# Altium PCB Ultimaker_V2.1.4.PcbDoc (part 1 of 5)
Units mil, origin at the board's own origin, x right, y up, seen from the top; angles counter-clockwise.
Board outline 6889.76 x 3110.24 mil, 4 copper layers (top, signal, Power, bot (thermal)), stack 67.717 mil thick; 574 components, 252 nets, 1322 pads, 511 vias.
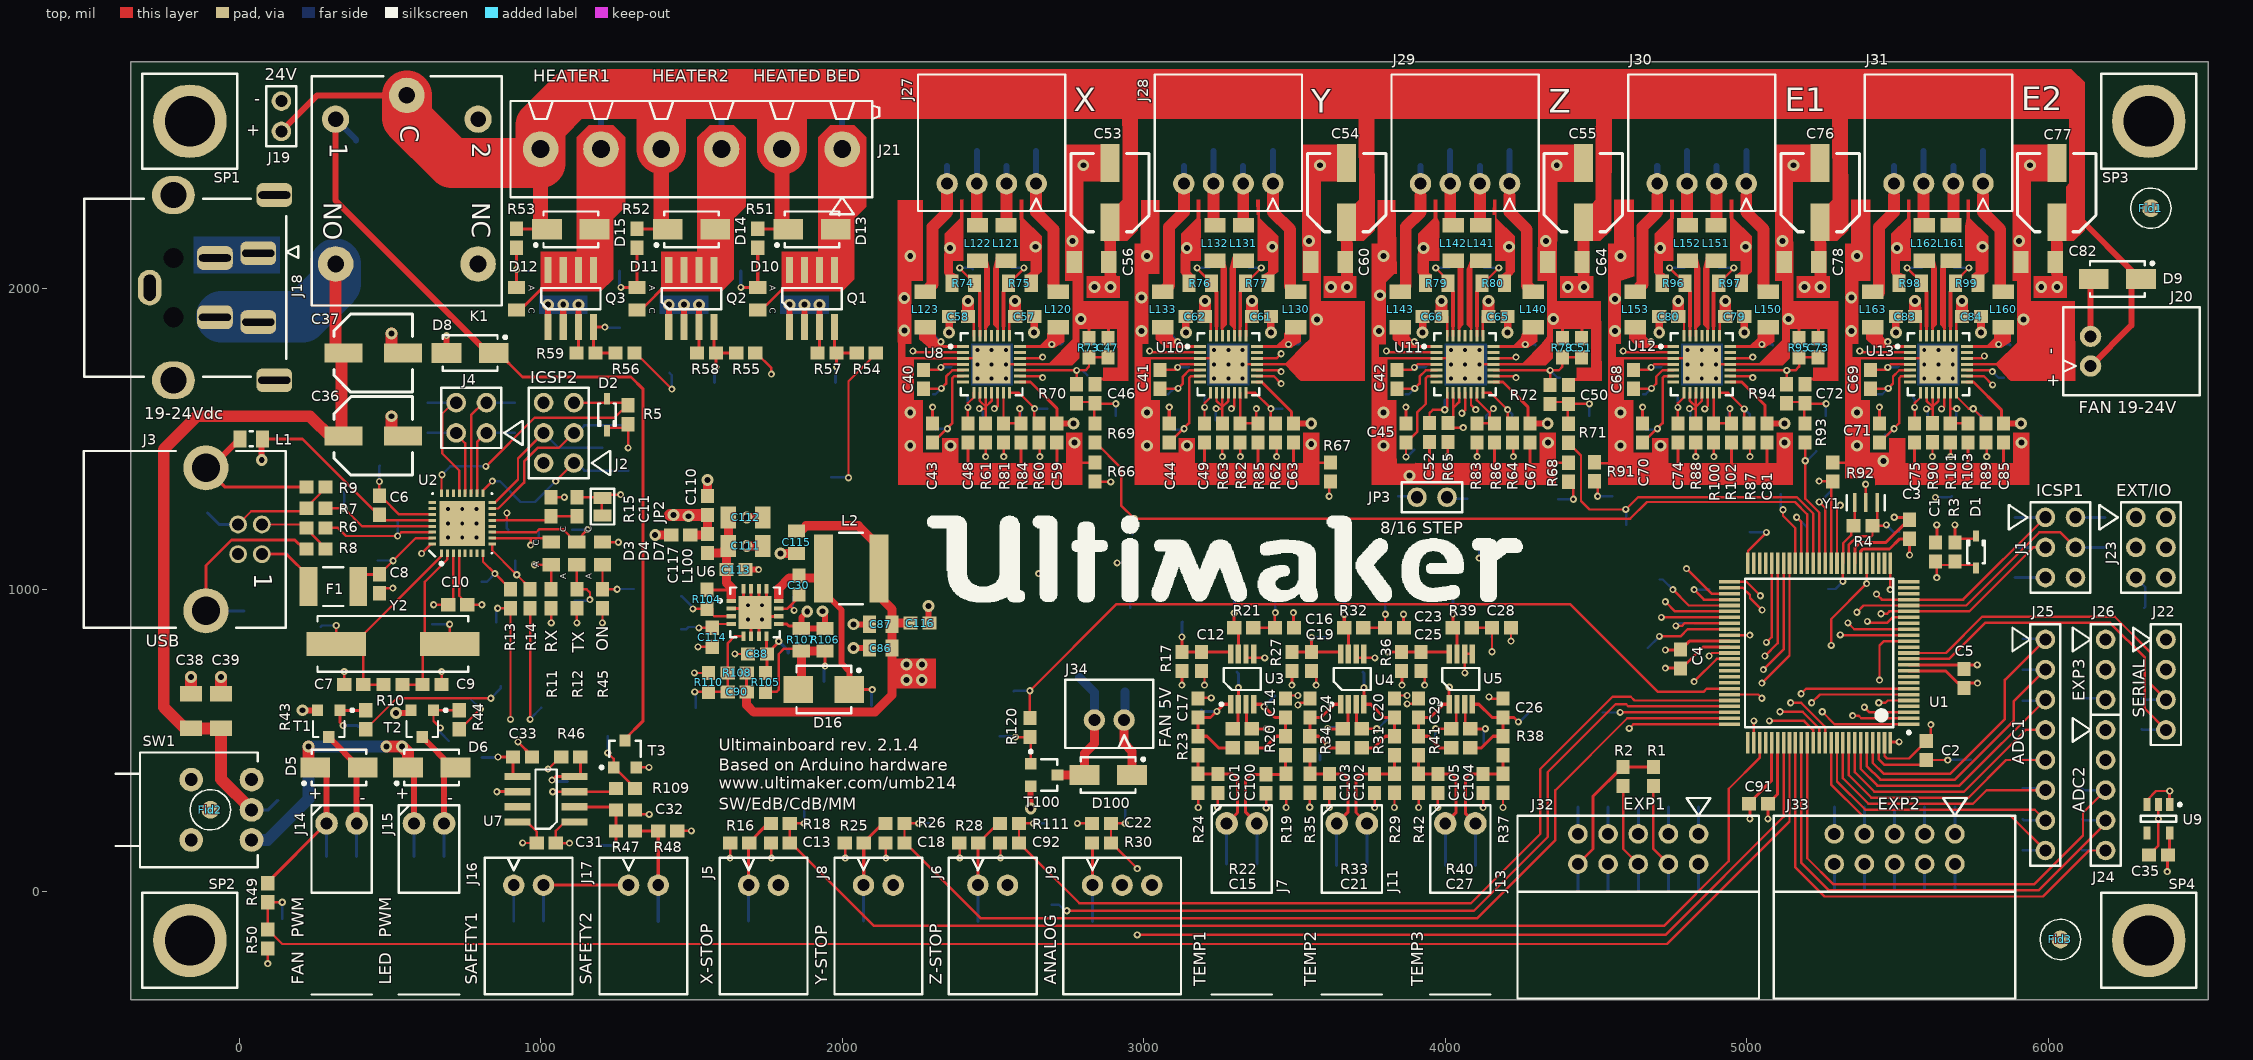
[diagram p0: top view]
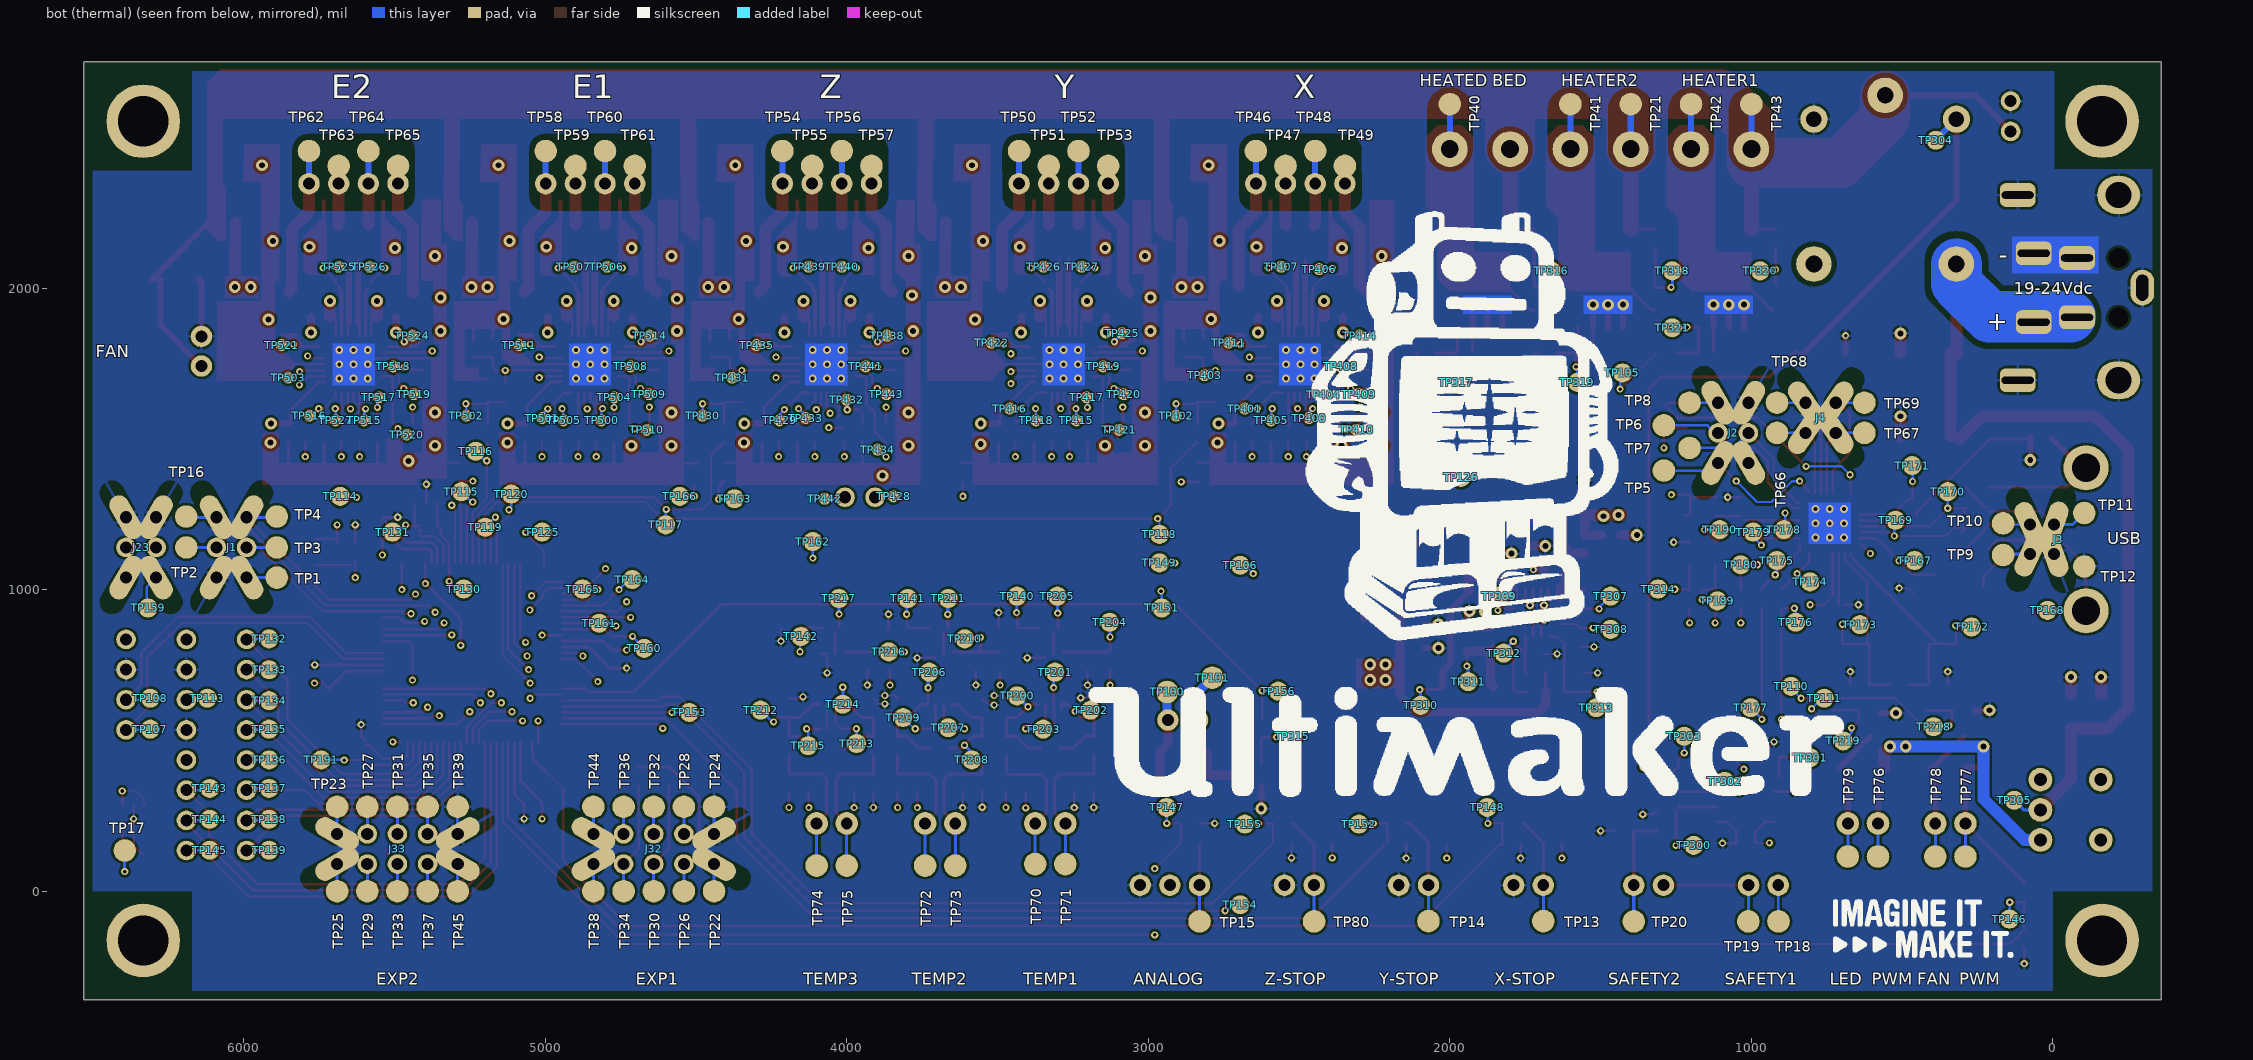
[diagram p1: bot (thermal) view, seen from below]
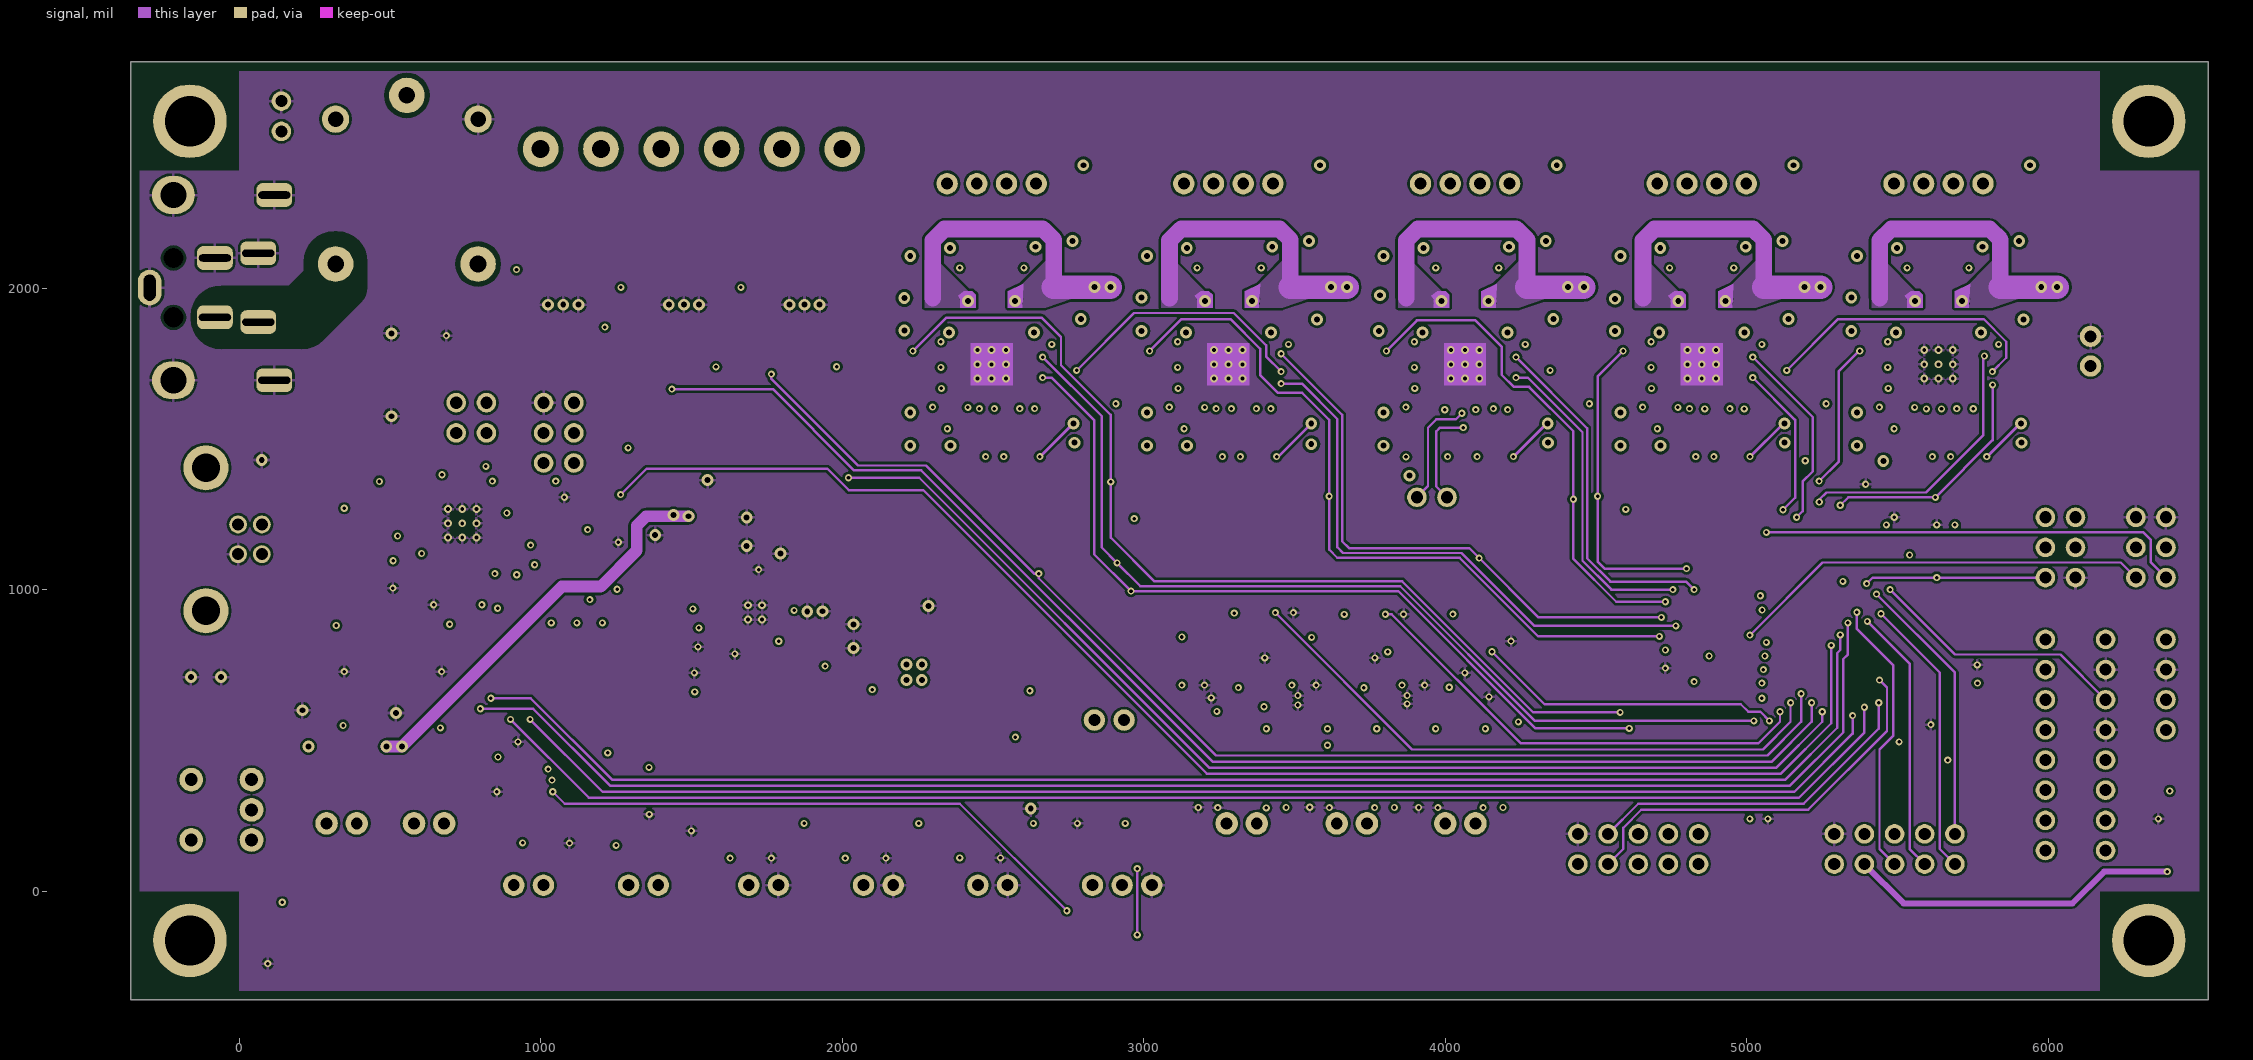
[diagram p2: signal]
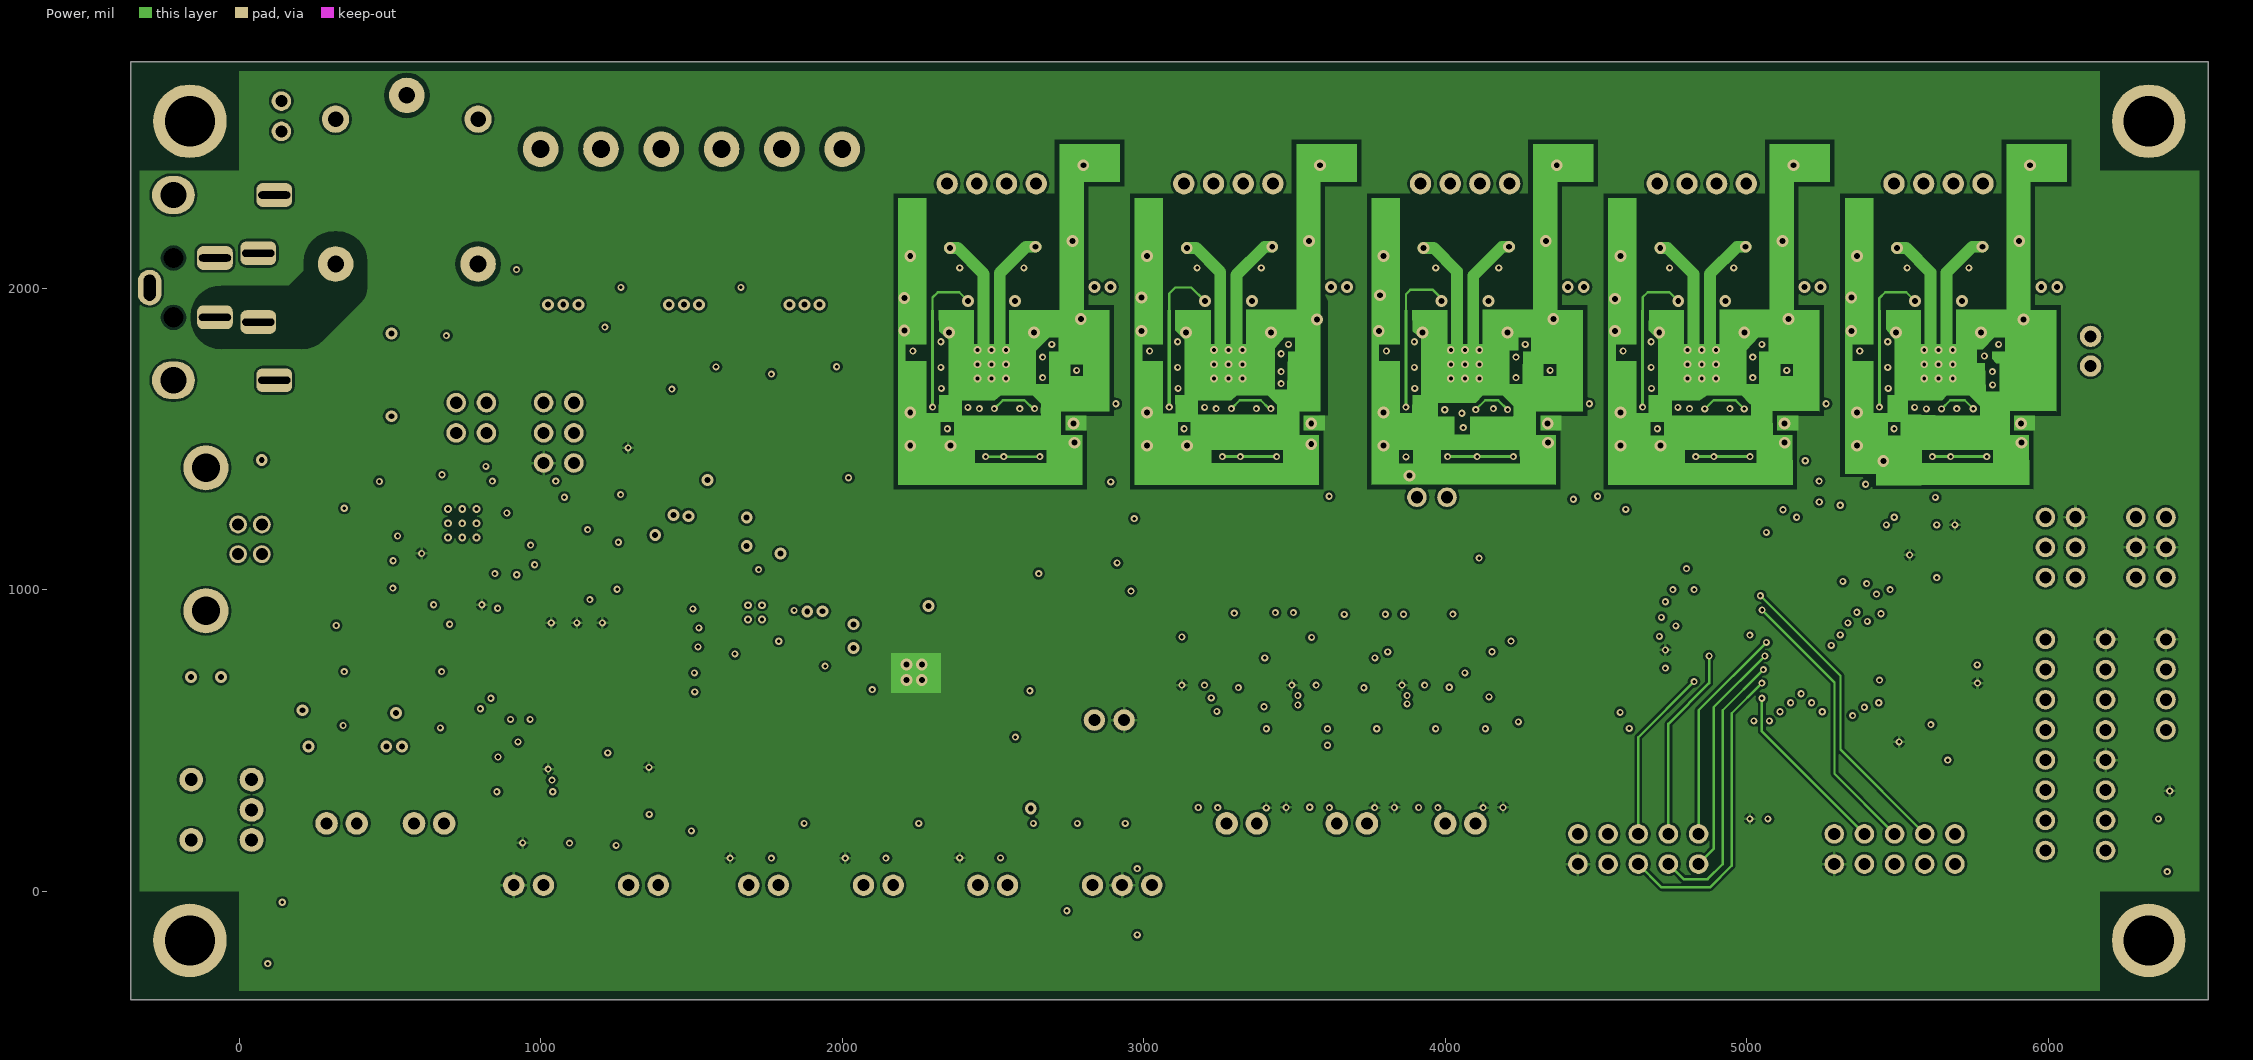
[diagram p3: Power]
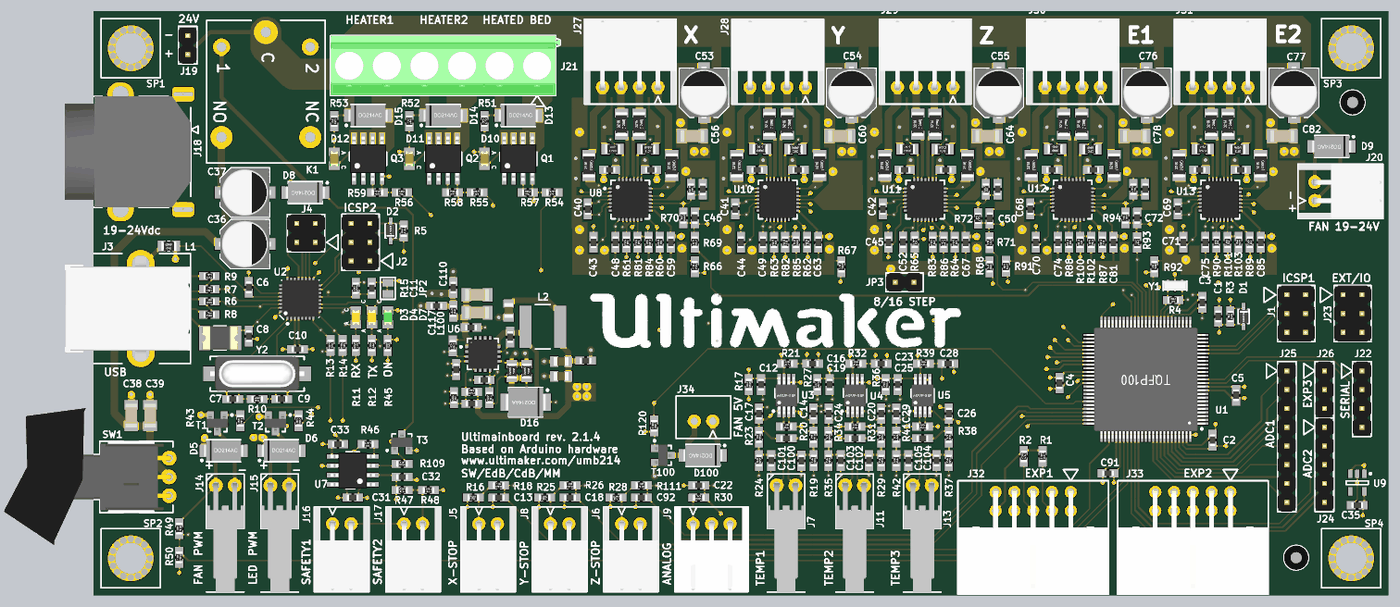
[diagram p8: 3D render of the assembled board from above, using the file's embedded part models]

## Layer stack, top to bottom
Top Solder: solder mask 0.4, Solder Resist, Dk 3.5
top: signal copper 2.7559
Dielectric1: prepreg 15.748, FR-4, Dk 4.8
signal: signal copper 1.378
Dielectric2: core 27.9528, FR-4, Dk 4.8
Power: signal copper 1.378
Dielectric3: prepreg 15.748, FR-4, Dk 4.8
bot (thermal): signal copper 2.7559
Bottom Solder: solder mask 0.4, Solder Resist, Dk 3.5

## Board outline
-360,-360 6529.76,-360 6529.76,2750.24 -360,2750.24

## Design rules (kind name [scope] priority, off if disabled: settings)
Clearance Clearance_U1 [InComponent('U1')] p1: gap=7
Clearance Clearance_U6 [InComponent('U6')] p2: gap=7
Clearance Clearance_U3,4,5 [InComponent('U3') or InComponent('U4') or InComponent('U5')] p3: gap=7
Clearance [All] p4: gap=8
HoleSize [All] p1: absolutevalues=TRUE maxlimit=169.29 minlimit=1 maxpercent=80.000 minpercent=20.000
MinimumSolderMaskSliver [All] p1 off: minsoldermaskwidth=2
PlaneClearance [All] p1: clearance=8
PlaneConnect [All] p1: planeconnectstyle=Relief reliefexpansion=8 reliefentries=4 reliefconductorwidth=8 reliefairgap=8
PolygonConnect [All] p1: connectstyle=Relief reliefconductorwidth=10 reliefentries=4 polygonreliefangle="90 Angle" airgapwidth=10
RoomDefinition schema5 [InComponentClass('schema5')] p1 off: confinementstyle=ConfineIn formatcopy=TRUE lockcomponents=FALSE outline 6572.97,-214.06 8738.32,-214.06 8738.32,26.09 6572.97,26.09
RoomDefinition schema4 [InComponentClass('schema4')] p2 off: confinementstyle=ConfineIn formatcopy=TRUE lockcomponents=FALSE outline -4990,-4155 -2990,-4155 -2990,-3155 -4990,-3155
RoomDefinition schema3 [InComponentClass('schema3')] p3 off: confinementstyle=ConfineIn formatcopy=TRUE lockcomponents=FALSE outline 6572.97,-300.68 6887.93,-300.68 6887.93,45.78 6572.97,45.78
RoomDefinition schema2 [InComponentClass('schema2')] p4 off: confinementstyle=ConfineIn formatcopy=TRUE lockcomponents=FALSE outline 6572.97,-403.04 8195.01,-403.04 8195.01,-162.88 6572.97,-162.88
RoomDefinition schema1 [InComponentClass('schema1')] p5 off: confinementstyle=ConfineIn formatcopy=TRUE lockcomponents=FALSE outline 6572.97,-300.68 6840.68,-300.68 6840.68,65.46 6572.97,65.46
RoutingVias [All] p1: holewidth=11.81 width=23.62 viastyle="Through Hole" minholewidth=11.81 minwidth=23.62 maxholewidth=39.37 maxwidth=118.11
SilkToSilkClearance [All] p1: silktosilkclearance=0
SilkToSolderMaskClearance SilkscreenOverComponentPads [IsPad] p1: minsilkscreentomaskgap=5 clearancetoexposedcopper=TRUE
SolderMaskExpansion [All] p1: expansion=4
Width [All] p1: maxlimit=393.7 minlimit=8 preferedwidth=8
24 further rules are at their usual default settings.

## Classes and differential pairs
component class schema5: C68 C69 C70 C71 C72 C73 C74 C75 C76 C77 C78 C79 C80 C81 C82 C83 C84 C85 J30 J31 L150 L151 L152 L153 L160 L161 L162 L163 R87 R88 R89 R90 R91 R92 R93 R94 R95 R96 R97 R98 R99 R100 R101 R102 R103 TP58 TP59 TP60 TP61 TP62 TP63 TP64 TP65 TP500 TP501 TP502 TP503 TP504 TP505 TP506 TP507 TP508 TP509 TP510 TP511 TP512 TP513 TP514 TP515 TP516 TP517 TP518 TP519 TP520 TP521 TP522 TP523 TP524 TP525 TP526 TP527 U12 U13
component class schema4: C40 C41 C42 C43 C44 C45 C46 C47 C48 C49 C50 C51 C52 C53 C54 C55 C56 C57 C58 C59 C60 C61 C62 C63 C64 C65 C66 C67 C120 C121 C122 C123 C130 C131 C132 C133 C140 C141 C142 C143 J27 J28 J29 JP3 L120 L121 L122 L123 L130 L131 L132 L133 L140 L141 L142 L143 R60 R61 R62 R63 R64 R65 R66 R67 R68 R69 R70 R71 R72 R73 R74 R75 R76 R77 R78 R79 R80 R81 R82 R83 R84 R85 R86 TP46 TP47 TP48 TP49 TP50 TP51 TP52 TP53 TP54 TP55 TP56 TP57 TP400 TP401 TP402 TP403 TP404 TP405 TP406 TP407 TP408 TP409 TP410 TP411 TP412 TP413 TP414 TP415 TP416 TP417 TP418 TP419 TP420 TP421 TP422 TP423 TP424 TP425 TP426 TP427 TP428 TP429 TP430 TP431 TP432 TP433 TP434 TP435 TP436 TP437 TP438 TP439 TP440 TP441 TP442 TP443 U8 U10 U11
component class schema2: C12 C13 C14 C15 C16 C17 C18 C19 C20 C21 C22 C23 C24 C25 C26 C27 C28 C29 C92 C100 C101 C102 C103 C104 C105 D5 D6 J5 J6 J7 J8 J9 J11 J13 J14 J15 R16 R17 R18 R19 R20 R21 R22 R23 R24 R25 R26 R27 R28 R29 R30 R31 R32 R33 R34 R35 R36 R37 R38 R39 R40 R41 R42 R43 R44 R111 T1 T2 TP13 TP14 TP15 TP70 TP71 TP72 TP73 TP74 TP75 TP76 TP77 TP78 TP79 TP80 TP200 TP201 TP202 TP203 TP204 TP205 TP206 TP207 TP208 TP209 TP210 TP211 TP212 TP213 TP214 TP215 TP216 TP217 TP218 TP219 U3 U4 U5
component class schema1: C1 C2 C3 C4 C5 C6 C7 C8 C9 C10 C11 C91 D1 D2 D3 D4 F1 Fid1 Fid2 Fid3 Fid? J1 J2 J3 J4 JP2 L1 R1 R2 R3 R4 R5 R6 R7 R8 R9 R10 R11 R12 R13 R14 R15 SP1 SP2 SP3 SP4 TP1 TP2 TP3 TP4 TP5 TP6 TP7 TP8 TP9 TP10 TP11 TP12 TP66 TP67 TP68 TP69 TP102 TP103 TP104 TP105 TP106 TP107 TP108 TP109 TP110 TP111 TP112 TP113 TP114 TP115 TP116 TP117 TP118 TP119 TP120 TP121 TP122 TP123 TP124 TP125 TP126 TP127 TP128 TP129 TP130 TP131 TP132 TP133 TP134 TP135 TP136 TP137 TP138 TP139 TP140 TP141 TP142 TP143 TP144 TP145 TP146 TP147 TP148 TP149 TP150 TP151 TP152 TP153 TP154 TP155 TP156 TP157 TP158 TP159 TP160 TP161 TP162 TP163 TP164 TP165 TP166 TP167 TP168 TP169 TP170 TP171 TP172 TP173 TP174 TP175 TP176 TP177 TP178 TP179 TP180 TP189 TP190 TP191 U1 U2 Y1 Y2
component class schema3: C30 C31 C32 C33 C35 C36 C37 C38 C39 C86 C87 C88 C90 C110 C111 C112 C113 C114 C115 C116 C117 D7 D8 D9 D10 D11 D12 D13 D14 D15 D16 D100 H1 H2 H3 H4 J16 J17 J18 J19 J20 J21 J22 J23 J24 J25 J26 J32 J33 J34 K1 L2 L100 Q1 Q2 Q3 R45 R46 R47 R48 R49 R50 R51 R52 R53 R54 R55 R56 R57 R58 R59 R104 R105 R106 R107 R108 R109 R110 R120 SW1 T3 T100 TP16 TP17 TP18 TP19 TP20 TP21 TP22 TP23 TP24 TP25 TP26 TP27 TP28 TP29 TP30 TP31 TP32 TP33 TP34 TP35 TP36 TP37 TP38 TP39 TP40 TP41 TP42 TP43 TP44 TP45 TP100 TP101 TP300 TP301 TP302 TP303 TP304 TP305 TP306 TP307 TP308 TP309 TP310 TP311 TP312 TP313 TP314 TP315 TP316 TP317 TP318 TP319 TP320 TP321 U6 U7 U9

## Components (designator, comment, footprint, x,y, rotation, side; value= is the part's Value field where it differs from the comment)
C1 "22pF" C0603 5625,1125 r270 top
C2 "100nF" C0603 5595,466.5 r270 top
C3 "100nF" C0603 5540,1200 r270 top
C4 "100nF" C0603 4780,770 r90 top
C5 "100nF" C0603 5720,705 r270 top
C6 "1uF" C0603 465,1280 r90 top
C7 "22pF" C0603 380,685 r0 top
C8 "100nF" C0603 465,1020 r90 top
C9 "22pF" C0603 640,685 r180 top
C10 "100nF" C0603 725,950 r0 top
C11 "100nF" C0603 1120,1275 r270 top
C12 "100nF" C0603 3191.5,762.17 r90 top
C13 "100nF" C0603 1795,160 r0 top
C14 "100nF" C0603 3470.64,607.39 r90 top
C15 "1uF" C0603 3326.5,475.66 r0 top
C16 "10nF" C0603 3466.5,873.66 r180 top
C17 "100nF" C0603 3180.64,607.39 r270 top
C18 "100nF" C0603 2175,160 r0 top
C19 "100nF" C0603 3556.5,762.17 r90 top
C20 "100nF" C0603 3831.5,607.39 r90 top
C21 "1uF" C0603 3691.5,475.66 r0 top
C22 "100nF" C0603 2860,225 r0 top
C23 "10nF" C0603 3831.5,873.66 r180 top
C24 "100nF" C0603 3551.5,607.39 r270 top
C25 "100nF" C0603 3919.5,762.16 r90 top
C26 "100nF" C0603 4191.5,607.39 r90 top
C27 "1uF" C0603 4051.5,475.66 r0 top
C28 "10nF" C0603 4186.5,873.66 r180 top
C29 "100nF" C0603 3911.5,607.39 r270 top
C30 "22nF" C0603 1856.54,1015.11 r270 top
C31 "100nF" C0603 1018.5,160 r180 top
C32 "100nF" C0603 1281.5,270 r180 top
C33 "10nF" C0603 940,445 r180 top
C35 "1uF" C0603 6365,120 r0 top
C36 "100uF/35V" "ELCO Case D" 445,1510 r180 top
C37 "100uF/35V" "ELCO Case D" 445,1785 r180 top
C38 "10uF" C1206 -160,597.09 r270 top
C39 "10uF" C1206 -60,597.09 r270 top
C40 "100nF" C0603 2269.64,1697.39 r270 top
C41 "100nF" C0603 3054.64,1697.39 r270 top
C42 "100nF" C0603 3839.64,1697.39 r270 top
C43 "100nF" C0603 2299.64,1519.9 r90 top
C44 "100nF" C0603 3084.64,1519.9 r90 top
C45 "100nF" C0603 3869.64,1519.9 r90 top
C46 "1uF" C0603 2839,1649.88 r270 top
C47 "1uF" C0603 2881.46,1802.51 r270 top
C48 "220nF" C0603 2416.64,1519.9 r90 top
C49 "220nF" C0603 3201.64,1519.9 r90 top
C50 "1uF" C0603 4408.64,1647.39 r270 top
C51 "1uF" C0603 4451.46,1802.51 r270 top
C52 "220nF" C0603 3947.64,1520.89 r90 top
C53 "100uF/35V" "ELCO Case D" 2888,2316.88 r270 top
C54 "100uF/35V" "ELCO Case D" 3673,2316.88 r270 top
C55 "100uF/35V" "ELCO Case D" 4458,2316.88 r270 top
C56 "4,7uF" C1206 2826.35,2085.98 r0 top
C57 "100nF" C0603 2605.64,1905.39 r180 top
C58 "100nF" C0603 2385.64,1905.39 r0 top
C59 "100nF" C0603 2711.64,1519.89 r90 top
C60 "4,7uF" C1206 3611.34,2085.98 r0 top
C61 "100nF" C0603 3390.15,1905.39 r180 top
C62 "100nF" C0603 3171.14,1905.39 r0 top
C63 "100nF" C0603 3496.64,1519.89 r90 top
C64 "4,7uF" C1206 4396.34,2085.98 r0 top
C65 "100nF" C0603 4175.15,1905.39 r180 top
C66 "100nF" C0603 3956.14,1905.39 r0 top
C67 "100nF" C0603 4281.64,1519.89 r90 top
C68 "100nF" C0603 4624.64,1697.39 r270 top
C69 "100nF" C0603 5409.64,1697.39 r270 top
C70 "100nF" C0603 4654.64,1519.9 r90 top
C71 "100nF" C0603 5439.64,1519.9 r90 top
C72 "1uF" C0603 5193.64,1649.89 r270 top
C73 "1uF" C0603 5236.46,1802.51 r270 top
C74 "220nF" C0603 4771.64,1519.9 r90 top
C75 "220nF" C0603 5556.64,1519.9 r90 top
C76 "100uF/35V" "ELCO Case D" 5243,2316.88 r270 top
C77 "100uF/35V" "ELCO Case D" 6028,2316.88 r270 top
C78 "4,7uF" C1206 5181.34,2085.98 r0 top
C79 "100nF" C0603 4960.15,1905.39 r180 top
C80 "100nF" C0603 4741.14,1905.39 r0 top
C81 "100nF" C0603 5066.64,1519.89 r90 top
C82 "4,7uF" C1206 5966.34,2085.98 r0 top
C83 "100nF" C0603 5526.14,1905.39 r0 top
C84 "100nF" C0603 5745.15,1905.39 r180 top
C85 "100nF" C0603 5851.64,1519.89 r90 top
C86 "10uF" C0805 2128.19,806.45 r0 top
C87 "10uF" C0805 2128.19,885.19 r0 top
C88 "1nF" C0603 1718.74,786.76 r0 top
C90 "10nF" C0603 1651.81,660.78 r0 top
C91 "100nF" C0603 5038.5,290 r180 top
C92 "100nF" C0603 2555,160 r0 top
C100 "100nF" C0603 3406.16,356.36 r270 top
C101 "100nF" C0603 3245.64,357.39 r90 top
C102 "100nF" C0603 3765.64,357.39 r270 top
C103 "100nF" C0603 3615.64,357.39 r90 top
C104 "100nF" C0603 4125.64,357.39 r270 top
C105 "100nF" C0603 3975.64,357.39 r90 top
C110 "100nF" C0603 1553.39,1278.89 r270 top
C111 "1uF" C1206 1679.37,1145.03 r180 top
C112 "1uF" C1206 1679.37,1239.52 r180 top
C113 "100nF" C0603 1647.88,1066.29 r180 top
C114 "22nF" C0603 1569.14,841.88 r90 top
C115 "10uF" C0805 1848.66,1156.84 r90 top
C116 "100nF" C0603 2258.11,889.13 r180 top
C117 "10nF" C0603 1464.57,1181.1 r0 top
D1 "1N4148" SOD323 5760,1125 r270 top
D2 "1N4148" SOD323 1220,1580 r90 top
D3 "Yellow" LED0805-YELLOW 1035,1120 r90 top
D4 "Yellow" LED0805-YELLOW 1120,1120 r90 top
D5 "S1G" "DO214AC (SMA)" 331.26,410 r180 top
D6 "S1G" "DO214AC (SMA)" 638.74,410 r180 top
D7 "Green" LED0805-GREEN 1205,1120 r90 top
D8 "S1G" "DO214AC (SMA)" 766.26,1785 r0 top
D9 "S1G" "DO214AC (SMA)" 6228.74,2030 r0 top
D10 "Red" LED0805-RED 1720,1965 r270 top
D11 "Red" LED0805-RED 1320,1965 r270 top
D12 "Red" LED0805-RED 920,1965 r270 top
D13 "S1G" "DO214AC (SMA)" 1900,2195 r180 top
D14 "S1G" "DO214AC (SMA)" 1500,2195 r180 top
D15 "S1G" "DO214AC (SMA)" 1100,2195 r180 top
D16 "SSB44-E3/52T" "DO214AA (SMB)" 1939.22,668.65 r0 top
D100 "S1G" "DO214AC (SMA)" 2882.13,385.19 r0 top
F1 "Multifuse" Multifuse1812 312.68,1010 r0 top
Fid1 "Fiducial" Fiducial 6340,2265 r0 top
Fid2 "Fiducial" Fiducial -95,270 r0 top
Fid3 "Fiducial" Fiducial 6040,-160 r0 top
J1 "HEADER-2x3P-ST-2.54" HEADER-2X3P-ST-2.54 5990,1240 r270 top
J2 "HEADER-2x3P-ST-2.54" HEADER-2X3P-ST-2.54 1110,1420 r90 top
J3 "61729-1011BLF" 61729-1011BLF -110,1404.02 r270 top locked
J4 "HEADER-2x2P-ST-2.54" HEADER-2X2P-ST-2.54 820,1520 r90 top
J5 "S2B-XH-A (LF)(SN)" "S2B-XH-A (LF)(SN)" 1739.21,20 r0 top
J6 "S2B-XH-A (LF)(SN)" "S2B-XH-A (LF)(SN)" 2499.21,20 r0 top
J7 "MOLEX-22-05-7028" MOLEX-22-05-7028 3325,225 r0 top
J8 "S2B-XH-A (LF)(SN)" "S2B-XH-A (LF)(SN)" 2120,20 r0 top
J9 "S3B-XH-A (LF)(SN)" "S3B-XH-A (LF)(SN)" 2830,20 r0 top
J11 "MOLEX-22-05-7028" MOLEX-22-05-7028 3690,225 r0 top
J13 "MOLEX-22-05-7028" MOLEX-22-05-7028 4050,225 r0 top
J14 "MOLEX-22-05-7028" MOLEX-22-05-7028 340,225 r0 top
J15 "MOLEX-22-05-7028" MOLEX-22-05-7028 630,225 r0 top
J16 "S2B-XH-A (LF)(SN)" "S2B-XH-A (LF)(SN)" 960,20 r0 top
J17 "S2B-XH-A (LF)(SN)" "S2B-XH-A (LF)(SN)" 1340.79,20 r0 top
J18 "KPJX-4S-S" KPJX-4S-S -217.8,2001.57 r90 top locked
J19 "HEADER 2" HEADER-1X2P-ST-2.54 140,2520 r0 top
J20 "S2B-XH-A (LF)(SN)" "S2B-XH-A (LF)(SN)" 6140,1790.79 r90 top
J21 "MC000038" MC000038 2000,2461 r180 top
J22 "HEADER 4" HEADER-1X4P-ST-2.54 6390,835 r270 top
J23 "HEADER-2x3P-ST-2.54" HEADER-2X3P-ST-2.54 6290,1240 r270 top
J24 "HEADER 5" HEADER-1X5P-ST-2.54 6190,535 r270 top
J25 "HEADER 8" HEADER-1X8P-ST-2.54 5990,835 r270 top
J26 "HEADER 3" HEADER-1X3P-ST-2.54 6190,835 r270 top
J27 "S4B-XH-A (LF)(SN)" "S4B-XH-A (LF)(SN)" 2495.64,2346.37 r180 top locked
J28 "S4B-XH-A (LF)(SN)" "S4B-XH-A (LF)(SN)" 3280.64,2346.37 r180 top locked
J29 "S4B-XH-A (LF)(SN)" "S4B-XH-A (LF)(SN)" 4065.64,2346.37 r180 top locked
J30 "S4B-XH-A (LF)(SN)" "S4B-XH-A (LF)(SN)" 4850.64,2346.37 r180 top locked
J31 "S4B-XH-A (LF)(SN)" "S4B-XH-A (LF)(SN)" 5635.64,2346.37 r180 top locked
J32 "BOXHEADER-10P-R/A-ST-2.54" BOXHEADER-10P-R/A-ST-2.54 4840,190 r180 top
J33 "BOXHEADER-10P-R/A-ST-2.54" BOXHEADER-10P-R/A-ST-2.54 5690,190 r180 top
J34 "B2B-XH-A (LF)(SN)" "B2B-XH-A (LF)(SN)" 2885.64,567.51 r0 top
JP2 "SOLDER JUMPER" "JUMPER 2 SOLDER" 1205,1275 r90 top
JP3 "HEADER 2" HEADER-1X2P-ST-2.54 3905.75,1306.45 r270 top
K1 "Relay-SPDT" HRS4-S 556.22,2639.06 r270 top
L1 "Bead" L0805 40,1500 r180 top
L2 "6,3uH / 3A" NRS6045 2029.77,1070.23 r0 top
L100 "120E @ 100MHz" R0603 1553.39,1152.91 r270 top
L120 "600E @ 100MHz" R1206 2716.54,1929.13 r90 top
L121 "600E @ 100MHz" R1206 2543.31,2149.61 r90 top
L122 "600E @ 100MHz" R1206 2448.82,2149.61 r90 top
L123 "600E @ 100MHz" R1206 2275.59,1929.13 r90 top
L130 "600E @ 100MHz" R1206 3503.94,1929.13 r90 top
L131 "600E @ 100MHz" R1206 3330.71,2149.61 r90 top
L132 "600E @ 100MHz" R1206 3236.22,2149.61 r90 top
L133 "600E @ 100MHz" R1206 3062.99,1929.13 r90 top
L140 "600E @ 100MHz" R1206 4291.34,1929.13 r90 top
L141 "600E @ 100MHz" R1206 4118.11,2149.61 r90 top
L142 "600E @ 100MHz" R1206 4026.27,2149.61 r90 top
L143 "600E @ 100MHz" R1206 3850.39,1929.13 r90 top
L150 "600E @ 100MHz" R1206 5070.87,1929.13 r90 top
L151 "600E @ 100MHz" R1206 4897.64,2149.61 r90 top
L152 "600E @ 100MHz" R1206 4803.15,2149.61 r90 top
L153 "600E @ 100MHz" R1206 4629.92,1929.13 r90 top
L160 "600E @ 100MHz" R1206 5850.39,1929.13 r90 top
L161 "600E @ 100MHz" R1206 5677.17,2149.61 r90 top
L162 "600E @ 100MHz" R1206 5588.39,2149.61 r90 top
L163 "600E @ 100MHz" R1206 5417.32,1929.13 r90 top
Q1 "IRF8736PBF" "SOIC127P600X175-8N (SO8)" 1900,1965 r90 top
Q2 "IRF8736PBF" "SOIC127P600X175-8N (SO8)" 1500,1965 r90 top
Q3 "IRF8736PBF" "SOIC127P600X175-8N (SO8)" 1100,1965 r90 top
R1 "10k" R0603 4690,380 r270 top
R2 "10k" R0603 4590,380 r270 top
R3 "10k" R0603 5690,1125 r90 top
R4 "1M" R0603 5385.4,1211.96 r180 top
R5 "10k" R0603 1290,1580 r90 top
R6 "22E" R0603 255,1205 r0 top
R7 "22E" R0603 255,1270 r0 top
R8 "20V" R0603 255,1135 r0 top
R9 "20V" R0603 255,1340 r0 top
R10 "1M" R0603 510,685 r180 top
R11 "1k" R0603 1035,970 r270 top
R12 "1k" R0603 1120,970 r270 top
R13 "1k" R0603 900,970 r270 top
R14 "1k" R0603 965,970 r270 top
R15 "1k" R0603 1035,1275 r90 top
R16 "4k7" R0603 1660,160 r180 top
R17 "100E" R0603 3126.5,762.17 r90 top
R18 "1k" R0603 1795,225 r0 top
R19 "2k2" R0603 3472.02,357.63 r90 top
R20 "10k" R0603 3470.64,482.39 r90 top
R21 "100E" R0603 3331.5,873.66 r0 top
R22 "5k49" R0603 3326.5,538.66 r0 top
R23 "10k" R0603 3180.64,482.39 r90 top
R24 "2k2" R0603 3180.68,357.63 r90 top
R25 "4k7" R0603 2040,160 r180 top
R26 "1k" R0603 2175,225 r0 top
R27 "100E" R0603 3491.5,762.17 r90 top
R28 "4k7" R0603 2420,160 r180 top
R29 "2k2" R0603 3831.5,357.63 r90 top
R30 "1k" R0603 2860,160 r0 top
R31 "10k" R0603 3831.5,482.39 r90 top
R32 "100E" R0603 3696.5,873.66 r0 top
R33 "5k49" R0603 3691.5,538.66 r0 top
R34 "10k" R0603 3550.64,482.39 r90 top
R35 "2k2" R0603 3550.76,357.63 r90 top
R36 "100E" R0603 3854.5,762.16 r90 top
R37 "2k2" R0603 4191.5,357.63 r90 top
R38 "10k" R0603 4191.5,482.39 r90 top
R39 "100E" R0603 4056.5,873.66 r0 top
R40 "5k49" R0603 4051.5,538.66 r0 top
R41 "10k" R0603 3911.5,482.39 r90 top
R42 "2k2" R0603 3911.5,357.63 r90 top
R43 "1k" R0603 420,568.5 r90 top
R44 "1k" R0603 730,568.5 r90 top
R45 "1k" R0603 1205,970 r270 top
R46 "10k" R0603 1100,445 r180 top
R47 "1k" R0603 1281.5,200 r180 top
R48 "1k" R0603 1421.5,200 r180 top
R49 "100k" R0603 95,-5 r90 top
R50 "4k7" R0603 95,-158.5 r90 top
R51 "1k" R0603 1720,2165 r90 top
R52 "1k" R0603 1320,2165 r90 top
R53 "1k" R0603 920,2165 r90 top
R54 "100E" R0603 2080,1785 r180 top
R55 "100E" R0603 1680,1785 r180 top
R56 "100E" R0603 1280,1785 r180 top
R57 "100k" R0603 1950,1785 r180 top
R58 "100k" R0603 1550,1785 r180 top
R59 "100k" R0603 1150,1785 r180 top
R60 "100k" R0603 2652.64,1519.89 r270 top
R61 "4k7" R0603 2475.64,1519.89 r270 top
R62 "100k" R0603 3437.64,1519.89 r270 top
R63 "4k7" R0603 3261,1519.88 r270 top
R64 "100k" R0603 4222.64,1519.89 r270 top
R65 "4k7" R0603 4009.64,1520.89 r270 top
R66 "100k" R0603 2839,1389.88 r90 top
R67 "100k" R0603 3620,1389.88 r90 top
R68 "100k" R0603 4408.64,1389.39 r90 top
R69 "1k" R0603 2839,1519.88 r90 top
R70 "1k" R0603 2777.64,1649.9 r90 top
R71 "1k" R0603 4408.64,1518.39 r90 top
R72 "1k" R0603 4346.64,1647.39 r90 top
R73 "604E" R0603 2818.47,1802.51 r270 top
R74 "0.05E" R0805 2402,2016 r0 top
R75 "0.05E" R0805 2589.55,2016 r180 top
R76 "0.05E" R0805 3187.5,2016 r0 top
R77 "0.05E" R0805 3374.5,2016 r180 top
R78 "604E" R0603 4388.47,1802.51 r270 top
R79 "0.05E" R0805 3971.5,2016 r0 top
R80 "0.05E" R0805 4159,2016 r180 top
R81 "NP" R0603 2534.64,1519.89 r270 top
R82 "NP" R0603 3319.64,1519.89 r270 top
R83 "NP" R0603 4104.64,1519.89 r270 top
R84 "10k" R0603 2593.64,1519.89 r90 top
R85 "10k" R0603 3378.64,1519.89 r90 top
R86 "10k" R0603 4163.64,1519.89 r90 top
R87 "100k" R0603 5007.64,1519.89 r270 top
R88 "4k7" R0603 4830.64,1519.89 r270 top
R89 "100k" R0603 5792.64,1519.89 r270 top
R90 "4k7" R0603 5615.95,1520.2 r270 top
R91 "100k" R0603 4495,1391.38 r90 top
R92 "100k" R0603 5285,1389.88 r90 top
R93 "1k" R0603 5193.64,1519.39 r90 top
R94 "1k" R0603 5131.64,1649.89 r90 top
R95 "604E" R0603 5173.47,1802.51 r270 top
R96 "0.05E" R0805 4756.91,2016 r0 top
R97 "0.05E" R0805 4944.4,2016 r180 top
R98 "0.05E" R0805 5542,2016 r0 top
R99 "0.05E" R0805 5729.5,2016 r180 top
R100 "NP" R0603 4889.64,1519.89 r270 top
R101 "NP" R0603 5674.64,1519.89 r270 top
R102 "10k" R0603 4948.64,1519.89 r90 top
R103 "10k" R0603 5733.64,1519.89 r90 top
R104 "100k" R0603 1551.42,967.87 r90 top
R105 "47E" R0603 1746.3,692.28 r270 top
R106 "0.1E" R0805 1943.15,834.01 r270 top
R107 "0.1E" R0805 1864.41,834.01 r270 top
R108 "3k92" R0603 1651.81,723.77 r0 top
R109 "1k" R0603 1281.5,340 r0 top
R110 "750E" R0603 1557.33,692.28 r270 top
R111 "1k" R0603 2555,225 r0 top
R120 "1k" R0603 2622.29,542.67 r270 top
SP1 "M3-10ET" "Spacer M3-10ET" -163.15,2553.39 r0 top locked
SP2 "M3-10ET" "Spacer M3-10ET" -163.15,-163.15 r0 top locked
SP3 "M3-10ET" "Spacer M3-10ET" 6332.91,2553.39 r0 top locked
SP4 "M3-10ET" "Spacer M3-10ET" 6332.91,-163.15 r0 top
SW1 "SW-SPDT" "RS 734-6918" 41.26,270 r270 top
T1 "BC817" SOT23 297.4,555.71 r180 top
T2 "BC817" SOT23 607.4,555.71 r180 top
T3 "BC807" SOT23 1280,455 r0 top
T100 "BC817" SOT23 2669.53,385.19 r270 top
TP1 "Testpoint" TESTPOINT 5890,1040 r180 bottom locked
TP2 "Testpoint" TESTPOINT 6190,1140 r90 bottom locked
TP3 "Testpoint" TESTPOINT 5890,1140 r90 bottom locked
TP4 "Testpoint" TESTPOINT 5890,1242.51 r90 bottom locked
TP5 "Testpoint" TESTPOINT 1290,1395 r90 bottom locked
TP6 "Testpoint" TESTPOINT 1290,1545 r90 bottom locked
TP7 "Testpoint" TESTPOINT 1205,1470 r90 bottom locked
TP8 "Testpoint" TESTPOINT 1205,1620 r90 bottom locked
TP9 "Testpoint" TESTPOINT 165,1115 r90 bottom locked
TP10 "Testpoint" TESTPOINT 165,1220 r90 bottom locked
TP11 "Testpoint" TESTPOINT -104.09,1254.17 r90 bottom locked
TP12 "Testpoint" TESTPOINT -104.09,1077.01 r90 bottom locked
TP13 "Testpoint" TESTPOINT 1690,-99.21 r90 bottom locked
TP14 "Testpoint" TESTPOINT 2070.79,-99.21 r90 bottom locked
TP15 "Testpoint" TESTPOINT 2830,-100 r90 bottom locked
TP16 "Testpoint" TESTPOINT 6190.63,1242.51 r90 bottom locked
TP17 "Testpoint" TESTPOINT 6394.37,135.16 r180 bottom locked
TP18 "Testpoint" TESTPOINT 910,-100 r270 bottom locked
TP19 "Testpoint" TESTPOINT 1010,-100 r270 bottom locked
TP20 "Testpoint" TESTPOINT 1390,-100 r270 bottom locked
TP21 "Testpoint" TESTPOINT 1400,2610 r90 bottom locked
TP22 "Testpoint" TESTPOINT 4440,0 r90 bottom locked
TP23 "Testpoint" TESTPOINT 5690,280 r90 bottom locked
TP24 "Testpoint" TESTPOINT 4440,280 r90 bottom locked
TP25 "Testpoint" TESTPOINT 5690,0 r90 bottom locked
TP26 "Testpoint" TESTPOINT 4540,0 r90 bottom locked
TP27 "Testpoint" TESTPOINT 5590,280 r90 bottom locked
TP28 "Testpoint" TESTPOINT 4540,280 r90 bottom locked
TP29 "Testpoint" TESTPOINT 5590,0 r90 bottom locked
TP30 "Testpoint" TESTPOINT 4640,0 r90 bottom locked
TP31 "Testpoint" TESTPOINT 5490,280 r90 bottom locked
TP32 "Testpoint" TESTPOINT 4640,280 r90 bottom locked
TP33 "Testpoint" TESTPOINT 5490,0 r90 bottom locked
TP34 "Testpoint" TESTPOINT 4740,0 r90 bottom locked
TP35 "Testpoint" TESTPOINT 5390,280 r90 bottom locked
TP36 "Testpoint" TESTPOINT 4740,280 r90 bottom locked
TP37 "Testpoint" TESTPOINT 5390,0 r90 bottom locked
TP38 "Testpoint" TESTPOINT 4840,0 r90 bottom locked
TP39 "Testpoint" TESTPOINT 5290,280 r90 bottom locked
TP40 "Testpoint" TESTPOINT 2000,2610 r90 bottom locked
TP41 "Testpoint" TESTPOINT 1600,2610 r90 bottom locked
TP42 "Testpoint" TESTPOINT 1200,2610 r90 bottom locked
TP43 "Testpoint" TESTPOINT 1000,2610 r90 bottom locked
TP44 "Testpoint" TESTPOINT 4840,280 r90 bottom locked
TP45 "Testpoint" TESTPOINT 5290,0 r90 bottom locked
TP46 "Testpoint" TESTPOINT 2643.28,2454.64 r270 bottom locked
TP47 "Testpoint" TESTPOINT 2544.85,2405.43 r270 bottom locked
TP48 "Testpoint" TESTPOINT 2446.43,2454.64 r270 bottom locked
TP49 "Testpoint" TESTPOINT 2348,2405.43 r270 bottom locked
TP50 "Testpoint" TESTPOINT 3428.28,2454.64 r270 bottom locked
TP51 "Testpoint" TESTPOINT 3329.85,2405.43 r270 bottom locked
TP52 "Testpoint" TESTPOINT 3231.43,2454.64 r270 bottom locked
TP53 "Testpoint" TESTPOINT 3133,2405.43 r270 bottom locked
TP54 "Testpoint" TESTPOINT 4213.28,2454.64 r90 bottom locked
TP55 "Testpoint" TESTPOINT 4114.85,2405.43 r90 bottom locked
TP56 "Testpoint" TESTPOINT 4016.43,2454.64 r90 bottom locked
TP57 "Testpoint" TESTPOINT 3918,2405.43 r90 bottom locked
TP58 "Testpoint" TESTPOINT 4998.28,2454.64 r270 bottom locked
TP59 "Testpoint" TESTPOINT 4899.85,2405.43 r90 bottom locked
TP60 "Testpoint" TESTPOINT 4801.43,2454.64 r90 bottom locked
TP61 "Testpoint" TESTPOINT 4703,2405.43 r90 bottom locked
TP62 "Testpoint" TESTPOINT 5783.28,2454.64 r90 bottom locked
TP63 "Testpoint" TESTPOINT 5684.85,2405.43 r90 bottom locked
TP64 "Testpoint" TESTPOINT 5586.43,2454.64 r90 bottom locked
TP65 "Testpoint" TESTPOINT 5488,2405.43 r90 bottom locked
TP66 "Testpoint" TESTPOINT 915,1520 r90 bottom locked
TP67 "Testpoint" TESTPOINT 625,1520 r90 bottom locked
TP68 "Testpoint" TESTPOINT 915,1620 r90 bottom locked
TP69 "Testpoint" TESTPOINT 625,1620 r90 bottom locked
TP70 "Testpoint" TESTPOINT 3375,90 r90 bottom locked
TP71 "Testpoint" TESTPOINT 3275,90 r90 bottom locked
TP72 "Testpoint" TESTPOINT 3740,85 r90 bottom locked
TP73 "Testpoint" TESTPOINT 3640,85 r90 bottom locked
TP74 "Testpoint" TESTPOINT 4100,85 r90 bottom locked
TP75 "Testpoint" TESTPOINT 4000,85 r90 bottom locked
TP76 "Testpoint" TESTPOINT 580,115 r90 bottom locked
TP77 "Testpoint" TESTPOINT 290,115 r90 bottom locked
TP78 "Testpoint" TESTPOINT 390,115 r90 bottom locked
TP79 "Testpoint" TESTPOINT 680,115 r90 bottom locked
TP80 "Testpoint" TESTPOINT 2450,-100 r90 bottom locked
TP100 "Testpoint" TESTPOINT 2937.25,660.78 r270 bottom locked
TP101 "Testpoint" TESTPOINT 2787.64,708.02 r270 bottom locked
TP105 "Testpoint 1.6mm" "TESTPOINT 1.6MM" 1427.4,1718.74 r270 bottom locked
TP106 "Testpoint 1.6mm" "TESTPOINT 1.6MM" 2695.12,1080.94 r270 bottom locked
TP107 "Testpoint 1.6mm" "TESTPOINT 1.6MM" 6309.29,537.64 r270 bottom locked
TP108 "Testpoint 1.6mm" "TESTPOINT 1.6MM" 6309.29,640 r270 bottom locked
TP110 "Testpoint 1.6mm" "TESTPOINT 1.6MM" 868.35,679.37 r270 bottom locked
TP111 "Testpoint 1.6mm" "TESTPOINT 1.6MM" 758.11,640 r270 bottom locked
TP113 "Testpoint 1.6mm" "TESTPOINT 1.6MM" 6120.32,640 r270 bottom locked
TP114 "Testpoint 1.6mm" "TESTPOINT 1.6MM" 5679.37,1309.29 r270 bottom locked
TP115 "Testpoint 1.6mm" "TESTPOINT 1.6MM" 5277.8,1325.04 r270 bottom locked
TP116 "Testpoint 1.6mm" "TESTPOINT 1.6MM" 5230.55,1458.9 r270 bottom locked
TP117 "Testpoint 1.6mm" "TESTPOINT 1.6MM" 4600.63,1214.8 r270 bottom locked
TP118 "Testpoint 1.6mm" "TESTPOINT 1.6MM" 2962.83,1183.31 r270 bottom locked
TP119 "Testpoint 1.6mm" "TESTPOINT 1.6MM" 5199.06,1206.93 r270 bottom locked
TP120 "Testpoint 1.6mm" "TESTPOINT 1.6MM" 5112.44,1317.17 r270 bottom locked
TP125 "Testpoint 1.6mm" "TESTPOINT 1.6MM" 5010.08,1191.18 r270 bottom locked
TP126 "Testpoint 1.6mm" "TESTPOINT 1.6MM" 1962.83,1372.28 r270 bottom locked
TP130 "Testpoint 1.6mm" "TESTPOINT 1.6MM" 5269.92,1002.2 r270 bottom locked
TP131 "Testpoint 1.6mm" "TESTPOINT 1.6MM" 5506.14,1191.18 r270 bottom locked
TP132 "Testpoint 1.6mm" "TESTPOINT 1.6MM" 5915.59,836.85 r270 bottom locked
TP133 "Testpoint 1.6mm" "TESTPOINT 1.6MM" 5915.59,734.49 r270 bottom locked
TP134 "Testpoint 1.6mm" "TESTPOINT 1.6MM" 5915.59,632.13 r270 bottom locked
TP135 "Testpoint 1.6mm" "TESTPOINT 1.6MM" 5915.59,537.64 r270 bottom locked
TP136 "Testpoint 1.6mm" "TESTPOINT 1.6MM" 5915.59,435.28 r270 bottom locked
TP137 "Testpoint 1.6mm" "TESTPOINT 1.6MM" 5915.59,340.79 r270 bottom locked
TP138 "Testpoint 1.6mm" "TESTPOINT 1.6MM" 5915.59,238.43 r270 bottom locked
TP139 "Testpoint 1.6mm" "TESTPOINT 1.6MM" 5915.59,136.06 r270 bottom locked
TP140 "Testpoint 1.6mm" "TESTPOINT 1.6MM" 3435.28,978.58 r270 bottom locked
TP141 "Testpoint 1.6mm" "TESTPOINT 1.6MM" 3797.48,970.71 r270 bottom locked
TP142 "Testpoint 1.6mm" "TESTPOINT 1.6MM" 4151.81,844.72 r270 bottom locked
TP143 "Testpoint 1.6mm" "TESTPOINT 1.6MM" 6112.44,340.79 r270 bottom locked
TP144 "Testpoint 1.6mm" "TESTPOINT 1.6MM" 6112.44,238.43 r270 bottom locked
TP145 "Testpoint 1.6mm" "TESTPOINT 1.6MM" 6112.44,136.06 r270 bottom locked
TP146 "Testpoint 1.6mm" "TESTPOINT 1.6MM" 143.94,-92.28 r270 bottom locked
TP147 "Testpoint 1.6mm" "TESTPOINT 1.6MM" 2939.21,277.8 r270 bottom locked
TP148 "Testpoint 1.6mm" "TESTPOINT 1.6MM" 1876.22,277.8 r270 bottom locked
TP149 "Testpoint 1.6mm" "TESTPOINT 1.6MM" 2962.83,1088.82 r270 bottom locked
TP151 "Testpoint 1.6mm" "TESTPOINT 1.6MM" 2954.96,939.21 r270 bottom locked
TP152 "Testpoint 1.6mm" "TESTPOINT 1.6MM" 2301.42,222.68 r270 bottom locked
TP153 "Testpoint 1.6mm" "TESTPOINT 1.6MM" 4521.89,592.76 r270 bottom locked
TP154 "Testpoint 1.6mm" "TESTPOINT 1.6MM" 2695.12,-45.04 r270 bottom locked
TP155 "Testpoint 1.6mm" "TESTPOINT 1.6MM" 2679.37,222.68 r270 bottom locked
TP156 "Testpoint 1.6mm" "TESTPOINT 1.6MM" 2569.13,663.62 r270 bottom locked
TP159 "Testpoint 1.6mm" "TESTPOINT 1.6MM" 6317.17,939.21 r270 bottom locked
TP160 "Testpoint 1.6mm" "TESTPOINT 1.6MM" 4671.5,805.35 r270 bottom locked
TP161 "Testpoint 1.6mm" "TESTPOINT 1.6MM" 4821.1,888.43 r270 bottom locked
TP162 "Testpoint 1.6mm" "TESTPOINT 1.6MM" 4112.44,1159.69 r270 bottom locked
TP163 "Testpoint 1.6mm" "TESTPOINT 1.6MM" 4372.28,1301.42 r270 bottom locked
TP164 "Testpoint 1.6mm" "TESTPOINT 1.6MM" 4710.87,1033.7 r270 bottom locked
TP165 "Testpoint 1.6mm" "TESTPOINT 1.6MM" 4876.22,1002.2 r270 bottom locked
TP166 "Testpoint 1.6mm" "TESTPOINT 1.6MM" 4553.39,1309.29 r270 bottom locked
TP167 "Testpoint 1.6mm" "TESTPOINT 1.6MM" 458.9,1096.69 r270 bottom locked
TP168 "Testpoint 1.6mm" "TESTPOINT 1.6MM" 17.95,931.34 r270 bottom locked
TP169 "Testpoint 1.6mm" "TESTPOINT 1.6MM" 521.89,1230 r270 bottom locked
TP170 "Testpoint 1.6mm" "TESTPOINT 1.6MM" 348.66,1325.04 r270 bottom locked
TP171 "Testpoint 1.6mm" "TESTPOINT 1.6MM" 466.77,1411.65 r270 bottom locked
TP172 "Testpoint 1.6mm" "TESTPOINT 1.6MM" 269.92,876.22 r270 bottom locked
TP173 "Testpoint 1.6mm" "TESTPOINT 1.6MM" 640,884.09 r270 bottom locked
TP174 "Testpoint 1.6mm" "TESTPOINT 1.6MM" 805.35,1025.83 r270 bottom locked
TP175 "Testpoint 1.6mm" "TESTPOINT 1.6MM" 915.59,1096.69 r270 bottom locked
TP176 "Testpoint 1.6mm" "TESTPOINT 1.6MM" 852.6,891.97 r270 bottom locked
TP177 "Testpoint 1.6mm" "TESTPOINT 1.6MM" 1002.2,608.5 r270 bottom locked
TP178 "Testpoint 1.6mm" "TESTPOINT 1.6MM" 891.97,1199.06 r270 bottom locked
TP179 "Testpoint 1.6mm" "TESTPOINT 1.6MM" 994.33,1191.18 r270 bottom locked
TP180 "Testpoint 1.6mm" "TESTPOINT 1.6MM" 1035,1082.6 r270 bottom locked
TP189 "Testpoint 1.6mm" "TESTPOINT 1.6MM" 1112.44,962.83 r270 bottom locked
TP190 "Testpoint 1.6mm" "TESTPOINT 1.6MM" 1104.57,1199.06 r270 bottom locked
TP191 "Testpoint 1.6mm" "TESTPOINT 1.6MM" 5742.36,435.28 r270 bottom locked
TP200 "Testpoint 1.6mm" "TESTPOINT 1.6MM" 3435.28,647.87 r270 bottom locked
TP201 "Testpoint 1.6mm" "TESTPOINT 1.6MM" 3309.29,726.61 r270 bottom locked
TP202 "Testpoint 1.6mm" "TESTPOINT 1.6MM" 3191.18,600.63 r270 bottom locked
TP203 "Testpoint 1.6mm" "TESTPOINT 1.6MM" 3348.66,537.64 r270 bottom locked
TP204 "Testpoint 1.6mm" "TESTPOINT 1.6MM" 3128.19,891.97 r270 bottom locked
TP205 "Testpoint 1.6mm" "TESTPOINT 1.6MM" 3301.42,978.58 r270 bottom locked
TP206 "Testpoint 1.6mm" "TESTPOINT 1.6MM" 3726.61,726.61 r270 bottom locked
TP207 "Testpoint 1.6mm" "TESTPOINT 1.6MM" 3663.43,542.1 r270 bottom locked
TP208 "Testpoint 1.6mm" "TESTPOINT 1.6MM" 3584.88,435.28 r270 bottom locked
TP209 "Testpoint 1.6mm" "TESTPOINT 1.6MM" 3813.23,575.9 r270 bottom locked
TP210 "Testpoint 1.6mm" "TESTPOINT 1.6MM" 3608.5,836.85 r270 bottom locked
TP211 "Testpoint 1.6mm" "TESTPOINT 1.6MM" 3663.62,970.71 r270 bottom locked
TP212 "Testpoint 1.6mm" "TESTPOINT 1.6MM" 4285.67,600.63 r270 bottom locked
TP213 "Testpoint 1.6mm" "TESTPOINT 1.6MM" 3967.38,489.75 r270 bottom locked
TP214 "Testpoint 1.6mm" "TESTPOINT 1.6MM" 4013.11,620 r270 bottom locked
TP215 "Testpoint 1.6mm" "TESTPOINT 1.6MM" 4128.19,482.52 r270 bottom locked
TP216 "Testpoint 1.6mm" "TESTPOINT 1.6MM" 3860.47,793.66 r270 bottom locked
TP217 "Testpoint 1.6mm" "TESTPOINT 1.6MM" 4025.83,970.71 r270 bottom locked
TP218 "Testpoint 1.6mm" "TESTPOINT 1.6MM" 395.91,545.51 r270 bottom locked
TP219 "Testpoint 1.6mm" "TESTPOINT 1.6MM" 695.12,498.27 r270 bottom locked
TP300 "Testpoint 1.6mm" "TESTPOINT 1.6MM" 1191.18,151.81 r270 bottom locked
TP301 "Testpoint 1.6mm" "TESTPOINT 1.6MM" 805.35,443.15 r270 bottom locked
TP302 "Testpoint 1.6mm" "TESTPOINT 1.6MM" 1088.82,364.41 r270 bottom locked
TP303 "Testpoint 1.6mm" "TESTPOINT 1.6MM" 1222.68,514.02 r270 bottom locked
TP304 "Testpoint 1.6mm" "TESTPOINT 1.6MM" 388.03,2490.39 r270 bottom locked
TP305 "Testpoint 1.6mm" "TESTPOINT 1.6MM" 128.19,301.42 r270 bottom locked
TP307 "Testpoint 1.6mm" "TESTPOINT 1.6MM" 1466.77,978.58 r270 bottom locked
TP308 "Testpoint 1.6mm" "TESTPOINT 1.6MM" 1466.77,868.35 r270 bottom locked
TP309 "Testpoint 1.6mm" "TESTPOINT 1.6MM" 1836.85,978.58 r270 bottom locked
TP310 "Testpoint 1.6mm" "TESTPOINT 1.6MM" 2096.69,616.38 r270 bottom locked
TP311 "Testpoint 1.6mm" "TESTPOINT 1.6MM" 1939.21,695.12 r270 bottom locked
TP312 "Testpoint 1.6mm" "TESTPOINT 1.6MM" 1821.1,789.61 r270 bottom locked
TP313 "Testpoint 1.6mm" "TESTPOINT 1.6MM" 1514.02,608.5 r270 bottom locked
TP314 "Testpoint 1.6mm" "TESTPOINT 1.6MM" 1309.29,1002.2 r270 bottom locked
TP315 "Testpoint 1.6mm" "TESTPOINT 1.6MM" 2521.89,514.02 r270 bottom locked
TP316 "Testpoint 1.6mm" "TESTPOINT 1.6MM" 1663.62,2057.32 r270 bottom locked
TP317 "Testpoint 1.6mm" "TESTPOINT 1.6MM" 1978.58,1687.24 r270 bottom locked
TP318 "Testpoint 1.6mm" "TESTPOINT 1.6MM" 1262.05,2057.32 r270 bottom locked
TP319 "Testpoint 1.6mm" "TESTPOINT 1.6MM" 1577.01,1687.24 r270 bottom locked
TP320 "Testpoint 1.6mm" "TESTPOINT 1.6MM" 970.71,2057.32 r270 bottom locked
TP321 "Testpoint 1.6mm" "Testpoint 1.6mm" 1262.05,1868.35 r270 bottom locked
TP400 "Testpoint 1mm" "Testpoint 1mm" 2466.77,1569.13 r270 bottom locked
TP401 "Testpoint 1mm" "Testpoint 1mm" 2679.37,1600.63 r270 bottom locked
TP402 "Testpoint 1mm" "Testpoint 1mm" 2907.72,1577.01 r270 bottom locked
TP403 "Testpoint 1mm" "Testpoint 1mm" 2813.23,1710.87 r270 bottom locked
TP404 "Testpoint 1mm" "Testpoint 1mm" 2417.32,1645.67 r270 bottom locked
TP405 "Testpoint 1mm" "Testpoint 1mm" 2592.76,1561.26 r270 bottom locked
TP406 "Testpoint 1mm" "Testpoint 1mm" 2433.07,2062.99 r270 bottom
TP407 "Testpoint 1mm" "Testpoint 1mm" 2559.06,2070.87 r270 bottom
TP408 "Testpoint 1mm" "Testpoint 1mm" 2362.2,1740.16 r270 bottom locked
TP409 "Testpoint 1mm" "Testpoint 1mm" 2301.42,1647.87 r270 bottom locked
TP410 "Testpoint 1mm" "Testpoint 1mm" 2309.29,1529.76 r270 bottom locked
TP411 "Testpoint 1mm" "Testpoint 1mm" 2732.28,1818.9 r270 bottom locked
TP414 "Testpoint 1mm" "Testpoint 1mm" 2299.21,1842.52 r270 bottom locked
TP415 "Testpoint 1mm" "Testpoint 1mm" 3238.43,1561.26 r270 bottom locked
TP416 "Testpoint 1mm" "Testpoint 1mm" 3458.9,1600.63 r270 bottom locked
TP417 "Testpoint 1mm" "Testpoint 1mm" 3204.72,1637.8 r270 bottom locked
TP418 "Testpoint 1mm" "Testpoint 1mm" 3372.28,1561.26 r270 bottom locked
TP419 "Testpoint 1mm" "Testpoint 1mm" 3149.61,1740.16 r270 bottom locked
TP420 "Testpoint 1mm" "Testpoint 1mm" 3080.94,1647.87 r270 bottom locked
TP421 "Testpoint 1mm" "Testpoint 1mm" 3096.69,1529.76 r270 bottom locked
TP422 "Testpoint 1mm" "Testpoint 1mm" 3519.68,1818.9 r270 bottom locked
TP425 "Testpoint 1mm" "Testpoint 1mm" 3086.61,1850.39 r270 bottom locked
TP426 "Testpoint 1mm" "Testpoint 1mm" 3346.46,2070.87 r270 bottom
TP427 "Testpoint 1mm" "Testpoint 1mm" 3220.47,2070.87 r270 bottom
TP428 "Testpoint 1mm" "Testpoint 1mm" 3844.72,1309.29 r270 bottom locked
TP429 "Testpoint 1mm" "Testpoint 1mm" 4222.68,1561.26 r270 bottom locked
TP430 "Testpoint 1mm" "Testpoint 1mm" 4477.71,1577.01 r270 bottom locked
TP431 "Testpoint 1mm" "Testpoint 1mm" 4380.16,1702.99 r270 bottom locked
TP432 "Testpoint 1mm" "Testpoint 1mm" 4000,1629.92 r270 bottom locked
TP433 "Testpoint 1mm" "Testpoint 1mm" 4136.06,1569.13 r270 bottom locked
TP434 "Testpoint 1mm" "Testpoint 1mm" 3897.64,1464.57 r270 bottom locked
TP435 "Testpoint 1mm" "Testpoint 1mm" 4299.21,1811.02 r270 bottom locked
TP438 "Testpoint 1mm" "Testpoint 1mm" 3866.14,1842.52 r270 bottom locked
TP439 "Testpoint 1mm" "Testpoint 1mm" 4125.98,2070.87 r270 bottom
TP440 "Testpoint 1mm" "Testpoint 1mm" 4015.75,2070.87 r270 bottom
TP441 "Testpoint 1mm" "Testpoint 1mm" 3937.01,1740.16 r270 bottom locked
TP442 "Testpoint 1mm" "Testpoint 1mm" 4073.07,1301.42 r270 bottom locked
TP443 "Testpoint 1mm" "Testpoint 1mm" 3868.35,1647.87 r270 bottom locked
TP500 "Testpoint 1mm" "Testpoint 1mm" 4813.23,1561.26 r270 bottom locked
TP501 "Testpoint 1mm" "Testpoint 1mm" 5010.08,1569.13 r270 bottom locked
TP502 "Testpoint 1mm" "Testpoint 1mm" 5262.05,1577.01 r270 bottom locked
TP503 "Testpoint 1mm" "Testpoint 1mm" 5852.6,1702.99 r270 bottom locked
TP504 "Testpoint 1mm" "Testpoint 1mm" 4771.65,1637.8 r270 bottom locked
TP505 "Testpoint 1mm" "Testpoint 1mm" 4939.21,1561.26 r270 bottom locked
TP506 "Testpoint 1mm" "Testpoint 1mm" 4795.28,2070.87 r270 bottom
TP507 "Testpoint 1mm" "Testpoint 1mm" 4905.51,2070.87 r270 bottom
TP508 "Testpoint 1mm" "Testpoint 1mm" 4716.54,1740.16 r270 bottom locked
TP509 "Testpoint 1mm" "Testpoint 1mm" 4655.75,1647.87 r270 bottom locked
TP510 "Testpoint 1mm" "Testpoint 1mm" 4663.62,1529.76 r270 bottom locked
TP511 "Testpoint 1mm" "Testpoint 1mm" 5086.61,1811.02 r270 bottom locked
TP514 "Testpoint 1mm" "Testpoint 1mm" 4653.54,1842.52 r270 bottom locked
TP515 "Testpoint 1mm" "Testpoint 1mm" 5600.63,1561.26 r270 bottom locked
TP516 "Testpoint 1mm" "Testpoint 1mm" 5781.73,1577.01 r270 bottom locked
TP517 "Testpoint 1mm" "Testpoint 1mm" 5551.18,1637.8 r270 bottom locked
TP518 "Testpoint 1mm" "Testpoint 1mm" 5503.94,1740.16 r270 bottom locked
TP519 "Testpoint 1mm" "Testpoint 1mm" 5435.28,1647.87 r270 bottom locked
TP520 "Testpoint 1mm" "Testpoint 1mm" 5458.9,1514.02 r270 bottom locked
TP521 "Testpoint 1mm" "Testpoint 1mm" 5874.02,1811.02 r270 bottom locked
TP524 "Testpoint 1mm" "Testpoint 1mm" 5440.94,1842.52 r270 bottom locked
TP525 "Testpoint 1mm" "Testpoint 1mm" 5685.04,2070.87 r270 bottom
TP526 "Testpoint 1mm" "Testpoint 1mm" 5582.68,2070.87 r270 bottom
TP527 "Testpoint 1mm" "Testpoint 1mm" 5695.12,1561.26 r270 bottom locked
U1 "ATMEGA2560-16AU" TSQFP50P1600X1600X120-100N 5240,790 r180 top
U2 "ATMEGA16U2-MU" QFN50P500X500X100-32-EX 740,1220 r90 top
U3 "INA826AIDGKR" "TSOP65P490X110-8N (MSOP8)" 3326.5,703.66 r90 top
U4 "INA826AIDGKR" "TSOP65P490X110-8N (MSOP8)" 3691.5,703.66 r90 top
U5 "INA826AIDGKR" "TSOP65P490X110-8N (MSOP8)" 4051.5,703.66 r90 top
U6 "A4403GEUTR-T" QFN65P400X400X80-16N-EX 1710.87,924.56 r0 top
U7 "NE555D" "SOIC127P600X175-8N (SO8)" 1018.23,305 r180 top
U8 "A4988" QFN50P500X500X100-28-EX 2495.64,1747.39 r0 top locked
U9 "LP2985A-33DBVTE4" "SOT95P280X145-5N (SOT23-5L)" 6365,240 r270 top
U10 "A4988" QFN50P500X500X100-28-EX 3280.63,1747.39 r0 top locked
U11 "A4988" QFN50P500X500X100-28-EX 4065.63,1747.39 r0 top locked
U12 "A4988" QFN50P500X500X100-28-EX 4850.63,1747.39 r0 top locked
U13 "A4988" QFN50P500X500X100-28-EX 5635.63,1747.39 r0 top locked
Y1 "16Mhz" CSTC 5395,1288.5 r0 top
Y2 "16MHz" XT49M-2016M 510,820 r180 top

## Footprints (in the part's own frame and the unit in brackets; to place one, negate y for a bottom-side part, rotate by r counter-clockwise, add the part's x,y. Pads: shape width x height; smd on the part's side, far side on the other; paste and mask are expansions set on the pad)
61729-1011BLF [mm]
  round 1.5 hole 1: 1(7.27,4.71) 2(4.77,4.71) 3(4.77,2.71) 4(7.27,2.71)
  oval 1.65x4 smd far side rot 115 paste-2 mask+0: 1(7.27,4.71)
  oval 1.65x4 smd far side rot 65 paste-2 mask+0: 2(4.77,4.71)
  oval 1.65x4 smd far side rot 110 paste-2 mask+0: 3(4.77,2.71)
  oval 1.65x4 smd far side rot 70 paste-2 mask+0: 4(7.27,2.71)
  round 3.8 hole 2.38 mask+0.102: 5(0,0) 5(12.04,0)
  silkscreen extent -1.42,-10.28 13.46,6.72, body extent -1.42,-10.28 13.46,6.72, height 11
"B2B-XH-A (LF)(SN)" [mm]
  round 1.8 hole 1: 1(1.25,0) 2(-1.25,0)
  silkscreen extent -3.7,-2.35 3.7,3.4, body extent -3.7,-2.35 3.7,3.41, height 7
BOXHEADER-10P-R/A-ST-2.54 [mm]
  round 1.65 hole 1.02: 1(0,0) 2(0,2.54) 3(2.54,0) 4(2.54,2.54) 5(5.08,0) 6(5.08,2.54) 7(7.62,0) 8(7.62,2.54) 9(10.16,0) 10(10.16,2.54)
  oval 1.65x4 smd far side rot 120 paste-2 mask+0: 1(0,0) 10(10.16,2.54)
  oval 1.65x4 smd far side rot 60 paste-2 mask+0: 2(0,2.54) 9(10.16,0)
  silkscreen extent -5.09,-3.02 15.26,13.86, body extent -5.08,-0.32 15.24,13.86, height 8.8
C0603 [mm] "Chip Capacitor, 2-Leads, Body 1.6x0.8mm, IPC Medium Density"
  rect 1.2x1.1 smd mask+0.102: 1(-0.8,0) 2(0.8,0)
  body extent -0.8,-0.4 0.8,0.4, height 0.9
C0805 [mm] "hip Capacitor, 2-Leads, Body 2,0x1.25mm, IPC Medium Density"
  rect 1.1x1.45 smd: 1(-0.95,0) 2(0.95,0)
  body extent -1,-0.6 1,0.6, height 1.2
C1206 [mm]
  rect 1.3x1.85 smd: 1(-1.45,0) 2(1.45,0)
  body extent -1.6,-0.8 1.6,0.8, height 0.77
CSTC [mm]
  rect 0.3x1.6 smd: 1(-0.95,0) 2(0,0) 3(0.95,0)
  silkscreen extent -1.6,-0.65 1.6,0.65, body extent -1.6,-0.65 1.6,0.65, height 1
"DO214AA (SMB)" [mm] "Molded Diode, 2-Leads, Body 4.3x3.6mm, IPC Medium Density"
  rect 2.5x2.3 smd: 1(-2.15,0) 2(2.15,0)
  silkscreen extent -2.3,-2 3.08,2, body extent -2.79,-1.97 2.79,1.97, height 2.61
"DO214AC (SMA)" [mm] "Molded Diode, 2-Leads, Body 4.3x2.6mm, IPC Medium Density"
  rect 2.5x1.7 smd: 1(-2,0) 2(2,0)
  silkscreen extent -2.3,-1.5 3.07,1.5, body extent -2.74,-1.4 2.74,1.4, height 2.3
"ELCO Case D" [mm]
  rect 3.2x1.6 smd: 1(2.5,0) 2(-2.5,0)
  silkscreen extent -3.3,-3.3 3.3,3.3, body extent -3.5,-3.3 3.5,3.3, height 5.41
Fiducial [mm] "Fiducial"
  round 1.5 smd mask+0.9: ""(0,0)
  silkscreen extent -1.7,-1.7 1.7,1.7
HEADER-1X2P-ST-2.54 [mm]
  round 1.65 hole 1.02: 1(0,0) 2(0,2.54)
  silkscreen extent -1.27,-1.27 1.27,3.81, body extent -1.25,-1.27 1.25,3.71, height 2.55
HEADER-1X3P-ST-2.54 [mm]
  round 1.65 hole 1.02: 1(0,0) 2(2.54,0) 3(5.08,0)
  silkscreen extent -1.27,-2.77 6.35,1.27, body extent -1.27,-1.25 6.25,1.25, height 8.2
HEADER-1X4P-ST-2.54 [mm]
  round 1.65 hole 1.02: 1(0,0) 2(2.54,0) 3(5.08,0) 4(7.62,0)
  silkscreen extent -1.27,-2.77 8.89,1.27, body extent -1.27,-1.25 8.79,1.25, height 8.3
HEADER-1X5P-ST-2.54 [mm]
  round 1.65 hole 1.02: 1(0,0) 2(2.54,0) 3(5.08,0) 4(7.62,0) 5(10.16,0)
  silkscreen extent -1.27,-2.77 11.43,1.27, body extent -1.27,-1.25 11.33,1.25, height 8.3
HEADER-1X8P-ST-2.54 [mm]
  round 1.65 hole 1.02: 1(0,0) 2(2.54,0) 3(5.08,0) 4(7.62,0) 5(10.16,0) 6(12.7,0) 7(15.24,0) 8(17.78,0)
  silkscreen extent -1.27,-2.77 19.05,1.27, body extent -1.17,-1.25 19.05,1.25, height 8.2
HEADER-2X2P-ST-2.54 [mm]
  round 1.65 hole 1.02: 1(0,0) 2(0,2.54) 3(2.54,0) 4(2.54,2.54)
  oval 1.65x4 smd far side rot 125 paste-2 mask+0: 1(0,0) 4(2.54,2.54)
  oval 1.65x4 smd far side rot 55 paste-2 mask+0: 2(0,2.54) 3(2.54,0)
  silkscreen extent -1.27,-3.08 3.79,3.79, body extent -1.27,-1.27 3.81,3.81, height 8.5
HEADER-2X3P-ST-2.54 [mm]
  round 1.65 hole 1.02: 1(0,0) 2(0,2.54) 3(2.54,0) 4(2.54,2.54) 5(5.08,0) 6(5.08,2.54)
  oval 1.65x4 smd far side rot 60 paste-2 mask+0: 2(0,2.54) 2(5.08,0)
  oval 1.65x4 smd far side rot 120 paste-2 mask+0: 4(0,0) 4(5.08,2.54)
  silkscreen extent -1.27,-3.08 6.35,3.79, body extent -1.27,-1.27 6.35,3.81, height 8.5
HRS4-S [mm]
  round 2.3 hole 1.3: 1(2,-6) 2(2,6)
  round 3 hole 1.4: 3(0,0) 4(14.2,-6) 5(14.2,6)
  silkscreen extent -1.6,-8 17.7,8, body extent -1.6,-7.9 17.7,7.9, height 15.8
"JUMPER 2 SOLDER" [mm]
  rect 1x1.5 smd: 1(-0.75,0) 2(0.75,0)
  silkscreen extent -1.5,-1 1.5,1
KPJX-4S-S [mm]
  round 0 hole 1.7 unplated: 0(-2.5,0) 0(2.5,0)
  rrect50% 2x3 hole 0.6 slot 2.7 at 90 deg: 1(2.9,-7.15) 2(-2.9,-7.15) 3(2.5,-3.5) 4(-2.5,-3.5) 5(-7.8,-8.5) 5(7.8,-8.5)
  oval 3.2x3.6 hole 2.2: 5(-7.8,0) 5(7.8,0)
  oval 3x2 hole 1 slot 2.2 at 0 deg: 5(0,2)
  silkscreen extent -7.5,-10.5 7.5,7.5, body extent -7.5,-9.5 7.5,7.5, height 15
L0805 [mm] "hip Bead, 2-Leads, Body 2,0x1.25mm, IPC Medium Density"
  rect 1.1x1.45 smd: 1(-0.95,0) 2(0.95,0)
  silkscreen extent -0.13,-0.64 0.13,0.64, body extent -1,-0.6 1,0.65, height 0.44
LED0805-GREEN [mm]
  rect 1.1x1.45 smd: 1(-0.95,0) 2(0.95,0)
  body extent -1.01,-0.62 1.01,0.63, height 1.1
LED0805-RED [mm]
  rect 1.1x1.45 smd: 1(-0.95,0) 2(0.95,0)
  body extent -1.01,-0.62 1.01,0.63, height 1.1
LED0805-YELLOW [mm]
  rect 1.1x1.45 smd: 1(-0.95,0) 2(0.95,0)
  body extent -1.01,-0.62 1.01,0.63, height 1.1
MC000038 [mm]
  round 3 hole 1.5: 1(0,0) 2(5.08,0) 3(10.16,0) 4(15.24,0) 5(20.32,0) 6(25.4,0)
  silkscreen extent -3.11,-4.05 27.94,5.5, body extent -3.11,-4.05 27.94,4.05, height 10.1
MOLEX-22-05-7028 [mm]
  round 1.9 hole 1: 1(-1.27,0) 2(1.27,0)
  silkscreen extent -2.54,-14.42 2.54,1.52, body extent -2.54,-14.42 2.54,0.32, height 5.87
Multifuse1812 [mm]
  rect 1.5x3.3 smd: 1(-2.1,0) 2(2.1,0)
  silkscreen extent -0.85,-1.63 0.85,1.63, body extent -2.41,-1.61 2.41,1.61, height 1.32
NRS6045 [mm]
  rect 1.6x5.7 smd: 1(-2.35,0) 2(2.35,0)
  silkscreen extent -1,-3 1,3, body extent -3,-3 3,3, height 4.5
QFN50P500X500X100-28-EX [mm] "QFN, 28-Leads, Body 5.2x5.2mm (max), Pitch 0.50mm, IPC Medium Density"
  rect 1x0.25 smd mask+0.15: 1(-2.4,1.5) 2(-2.4,1) 3(-2.4,0.5) 4(-2.4,0) 5(-2.4,-0.5) 6(-2.4,-1) 7(-2.4,-1.5) 15(2.4,-1.5) 16(2.4,-1) 17(2.4,-0.5) 18(2.4,0) 19(2.4,0.5) 20(2.4,1) 21(2.4,1.5)
  rect 0.25x1 smd mask+0.15: 8(-1.5,-2.4) 9(-1,-2.4) 10(-0.5,-2.4) 11(0,-2.4) 12(0.5,-2.4) 13(1,-2.4) 14(1.5,-2.4) 22(1.5,2.4) 23(1,2.4) 24(0.5,2.4) 25(0,2.4) 26(-0.5,2.4) 27(-1,2.4) 28(-1.5,2.4)
  rect 3.2x3.2 smd mask+0.15: EXPAD(0,0)
  silkscreen extent -3.57,-2.6 2.6,2.6, body extent -2.52,-2.52 2.52,2.52, height 0.9
QFN50P500X500X100-32-EX [mm] "QFN, 32-Leads, Body 5.0x5.0mm (max), Pitch 0.50mm, IPC Medium Density"
  rect 0.65x0.25 smd mask+0.13: 1(-2.525,1.75) 2(-2.525,1.25) 3(-2.525,0.75) 4(-2.525,0.25) 5(-2.525,-0.25) 6(-2.525,-0.75) 7(-2.525,-1.25) 8(-2.525,-1.75) 17(2.525,-1.75) 18(2.525,-1.25) 19(2.525,-0.75) 20(2.525,-0.25) 21(2.525,0.25) 22(2.525,0.75) 23(2.525,1.25) 24(2.525,1.75)
  rect 0.25x0.65 smd mask+0.13: 9(-1.75,-2.525) 10(-1.25,-2.525) 11(-0.75,-2.525) 12(-0.25,-2.525) 13(0.25,-2.525) 14(0.75,-2.525) 15(1.25,-2.525) 16(1.75,-2.525) 25(1.75,2.525) 26(1.25,2.525) 27(0.75,2.525) 28(0.25,2.525) 29(-0.25,2.525) 30(-0.75,2.525) 31(-1.25,2.525) 32(-1.75,2.525)
  rect 3.8x3.8 smd mask+0.18: EXPAD(0,0)
  silkscreen extent -3.52,-2.52 2.52,2.79, body extent -2.5,-2.5 2.5,2.5, height 0.84
QFN65P400X400X80-16N-EX [mm] "QFN, 16-Leads, Body 4.2x4.2mm (max), Pitch 0.65mm, IPC Medium Density"
  rect 0.8x0.35 smd mask+0.15: 1(-2,0.975) 2(-2,0.325) 3(-2,-0.325) 4(-2,-0.975) 9(2,-0.975) 10(2,-0.325) 11(2,0.325) 12(2,0.975)
  rect 0.35x0.8 smd mask+0.15: 5(-0.975,-2) 6(-0.325,-2) 7(0.325,-2) 8(0.975,-2) 13(0.975,2) 14(0.325,2) 15(-0.325,2) 16(-0.975,2)
  rect 2.8x2.8 smd: EXPAD(0,0)
  silkscreen extent -3.07,-2.1 2.1,2.1, body extent -2,-2 2,2, height 0.92
R0603 [mm] "hip Resistor, 2-Leads, Body 1.55x0.85mm, IPC Medium Density"
  rect 1.2x1.1 smd mask+0.102: 1(-0.8,0) 2(0.8,0)
  body extent -0.77,-0.42 0.78,0.43, height 0.45
R0805 [mm] "hip Resistor, 2-Leads, Body 2,0x1.25mm, IPC Medium Density"
  rect 1.1x1.45 smd mask+0.203: 1(-0.95,0) 2(0.95,0)
  body extent -1,-0.6 1,0.65, height 0.44
R1206 [mm] "Chip Resistor, 2-Leads, Body 3,2x1,6mm, IPC Medium Density"
  rect 1.2x1.8 smd: 1(-1.5,0) 2(1.5,0)
  body extent -1.6,-0.8 1.6,0.8, height 0.55
"RS 734-6918" [mm]
  round 2 hole 1.09: 0(-2.54,-5.08) 0(2.54,-5.08) 1(2.54,0) 2(0,0) 3(-2.54,0)
  silkscreen extent -4.83,-11.43 4.83,0.51, body extent -9.31,-22.27 9.2,0.3, height 2.63
"S2B-XH-A (LF)(SN)" [mm]
  round 1.8 hole 1: 1(-1.25,0) 2(1.25,0)
  silkscreen extent -3.7,-9.2 3.7,2.3, body extent -3.7,-9.2 3.7,2.3, height 6.1
"S3B-XH-A (LF)(SN)" [mm]
  round 1.8 hole 1: 1(0,0) 2(2.5,0) 3(5,0)
  silkscreen extent -2.45,-9.2 7.46,2.3, body extent -2.45,-9.2 7.45,2.3, height 6.1
"S4B-XH-A (LF)(SN)" [mm]
  round 1.8 hole 1: 1(-3.75,0) 2(-1.25,0) 3(1.25,0) 4(3.75,0)
  silkscreen extent -6.2,-9.2 6.2,2.3, body extent -6.2,-9.2 6.2,2.3, height 6.1
SOD323 [mm] "SOD-323/SC-76; 2 Leads; Body 1.7 x 1.3 mm, (LxW)"
  rect 0.95x0.5 smd: 1(1.35,0) 2(-1.35,0)
  silkscreen extent -0.95,-0.75 0.95,0.75, body extent -1.25,-0.62 1.25,0.63, height 0.98
"SOIC127P600X175-8N (SO8)" [mm] "SOIC, 8-Leads, Body 5,0x4,0mm (max), Pitch 1,27mm, IPC Medium Density"
  rect 2.2x0.6 smd: 1(-2.4,1.905) 2(-2.4,0.635) 3(-2.4,-0.635) 4(-2.4,-1.905) 5(2.4,-1.905) 6(2.4,-0.635) 7(2.4,0.635) 8(2.4,1.905)
  silkscreen extent -0.9,-2.5 0.9,2.5, body extent -3,-2.45 3,2.45, height 1.75
SOT23 [mm] "SOT-23; 3 Leads; Body 3.0 x 2.5 mm, inc. leads (LxW max)"
  rect 0.95x1 smd: 1(-0.95,-1.125) 2(0.95,-1.125) 3(0,1.125)
  silkscreen extent -2.1,-1.25 1.32,1.13, body extent -1.46,-1.25 1.46,1.23, height 0.99
"SOT95P280X145-5N (SOT23-5L)" [mm] "SOT23, 5-Leads, Body 3.0x3.0mm (max), Pitch 0.95mm, IPC Medium Density"
  rect 1.1x0.6 smd: 1(-1.2,0.95) 2(-1.2,0) 3(-1.2,-0.95) 4(1.2,-0.95) 5(1.2,0.95)
  silkscreen extent -1.32,-1.5 0.25,1.93, body extent -0.87,-1.5 0.87,1.5, height 1.45
"Spacer M3-10ET" [mm] "Spacer M3-10ET"
  round 6.2 hole 4.22: 0(0,0)
TESTPOINT [mm]
  round 1.9 smd paste-2 mask+0: 1(0,0)
"TESTPOINT 1.6MM" [mm]
  round 1.6 smd paste-2 mask+0: 1(0,0)
"Testpoint 1.6mm" [mm]
  round 1.6 smd paste-2 mask+0: 1(0,0)
"Testpoint 1mm" [mm]
  round 1 smd paste-2 mask+0: 1(0,0)
"TSOP65P490X110-8N (MSOP8)" [mm] "TSOP, 8-Leads, Body 3.1x3.1mm (max), Pitch 0.65mm, IPC Medium Density"
  rect 1.6x0.45 smd: 1(-2.125,0.975) 2(-2.125,0.325) 3(-2.125,-0.325) 4(-2.125,-0.975) 5(2.125,-0.975) 6(2.125,-0.325) 7(2.125,0.325) 8(2.125,0.975)
  silkscreen extent -2.25,-1.55 0.92,1.87, body extent -2.5,-1.5 2.5,1.5, height 1.09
